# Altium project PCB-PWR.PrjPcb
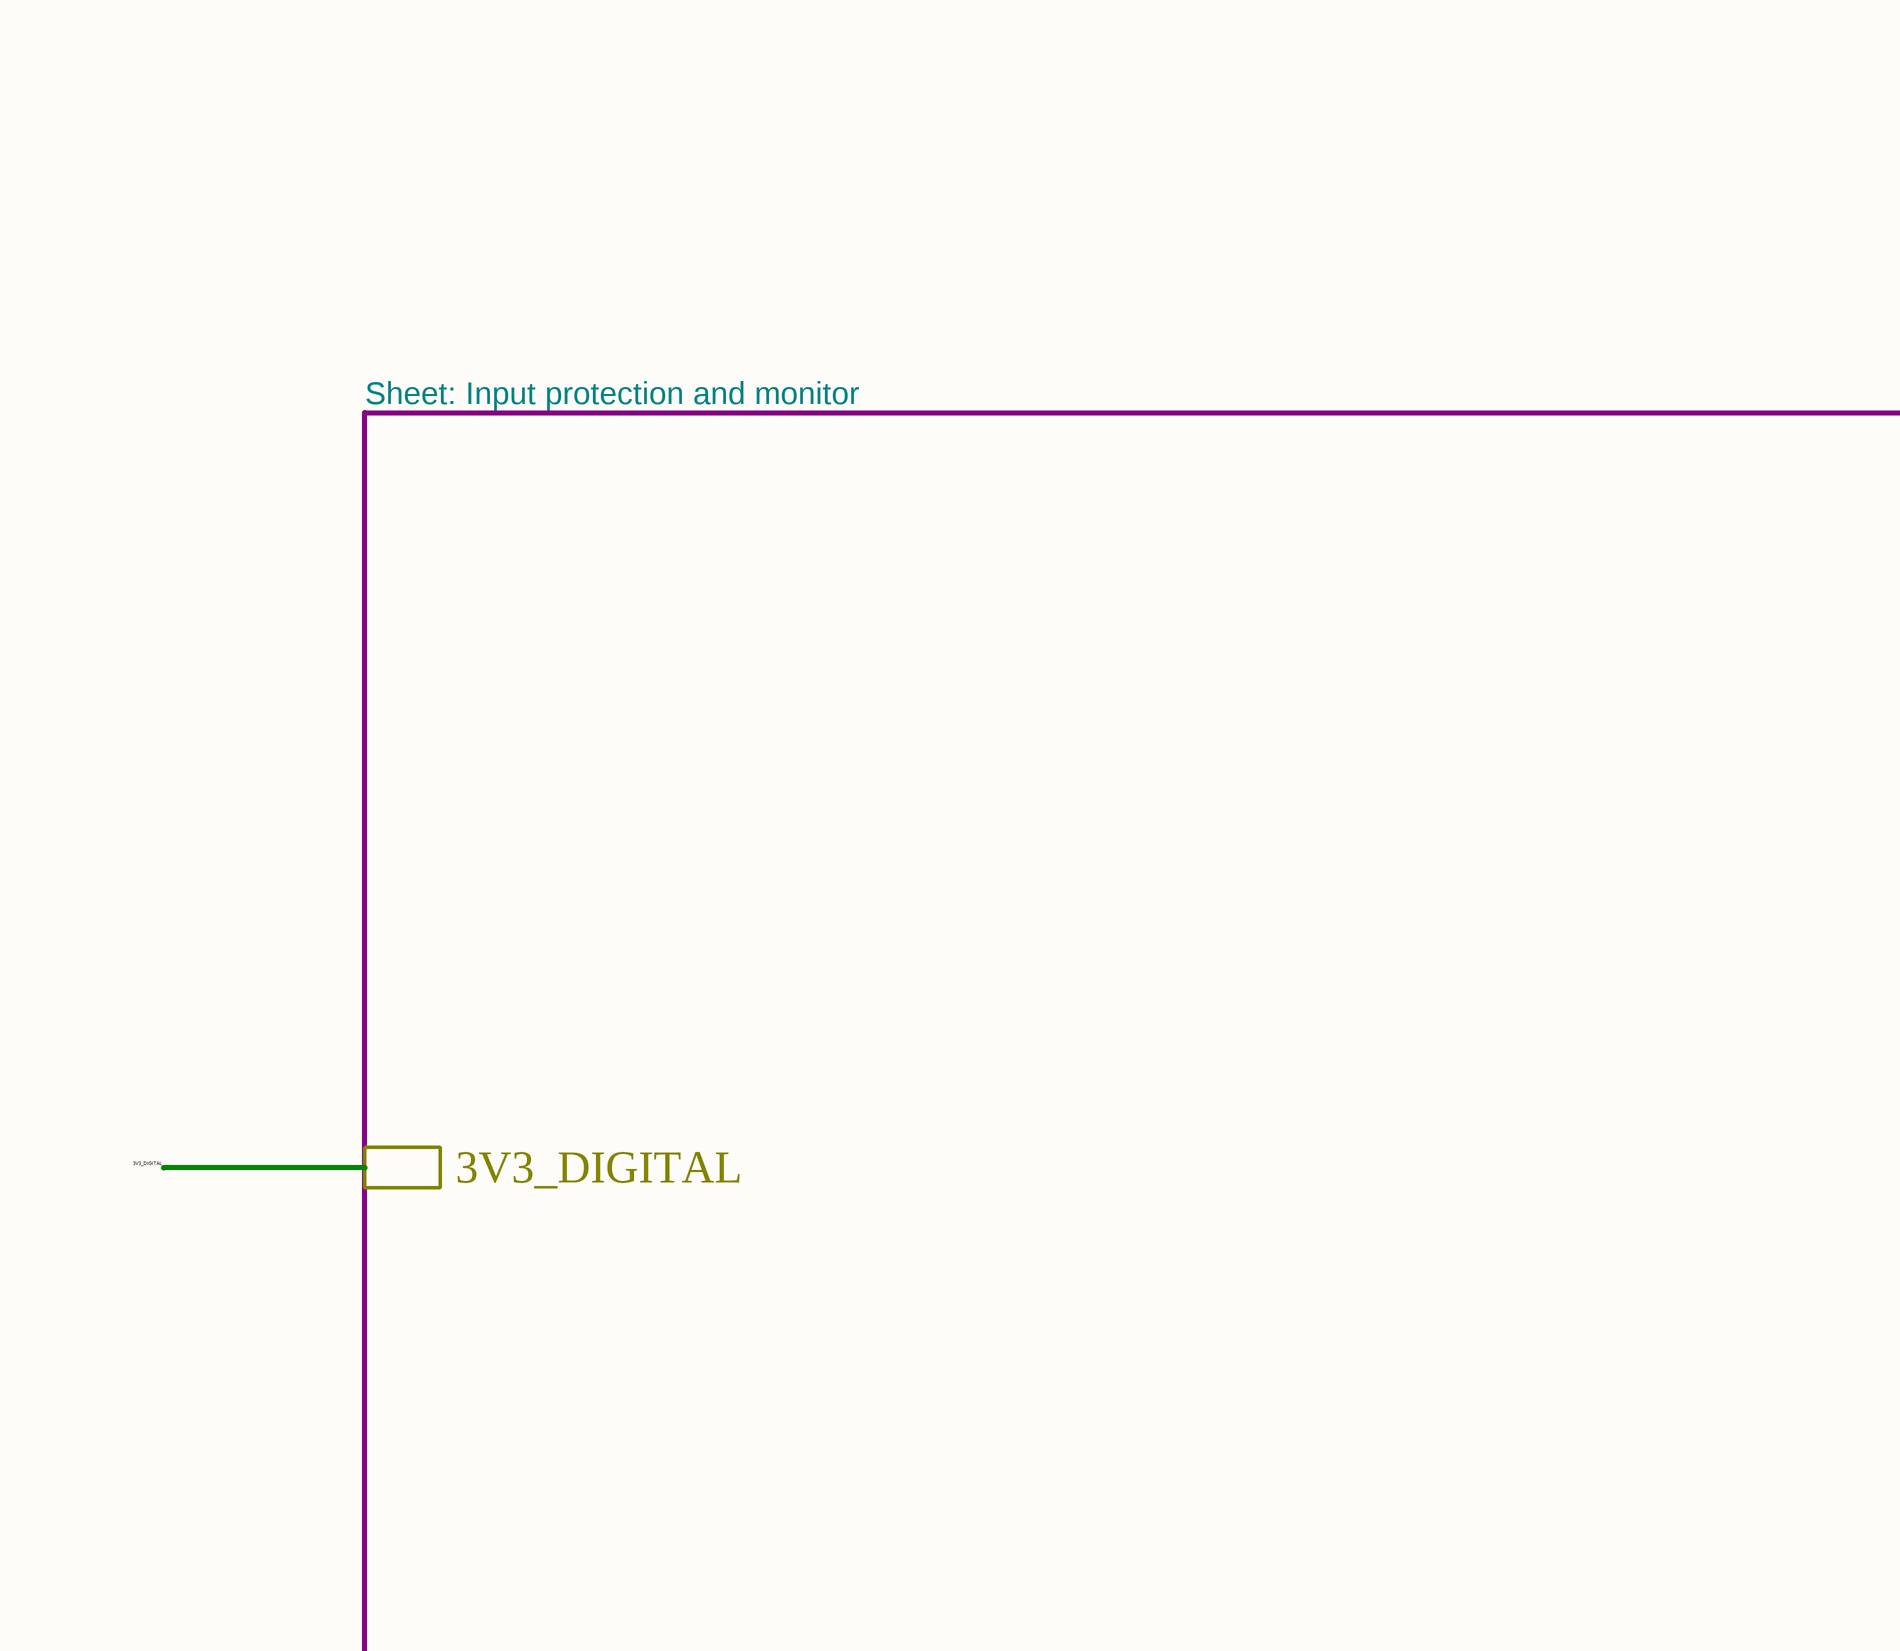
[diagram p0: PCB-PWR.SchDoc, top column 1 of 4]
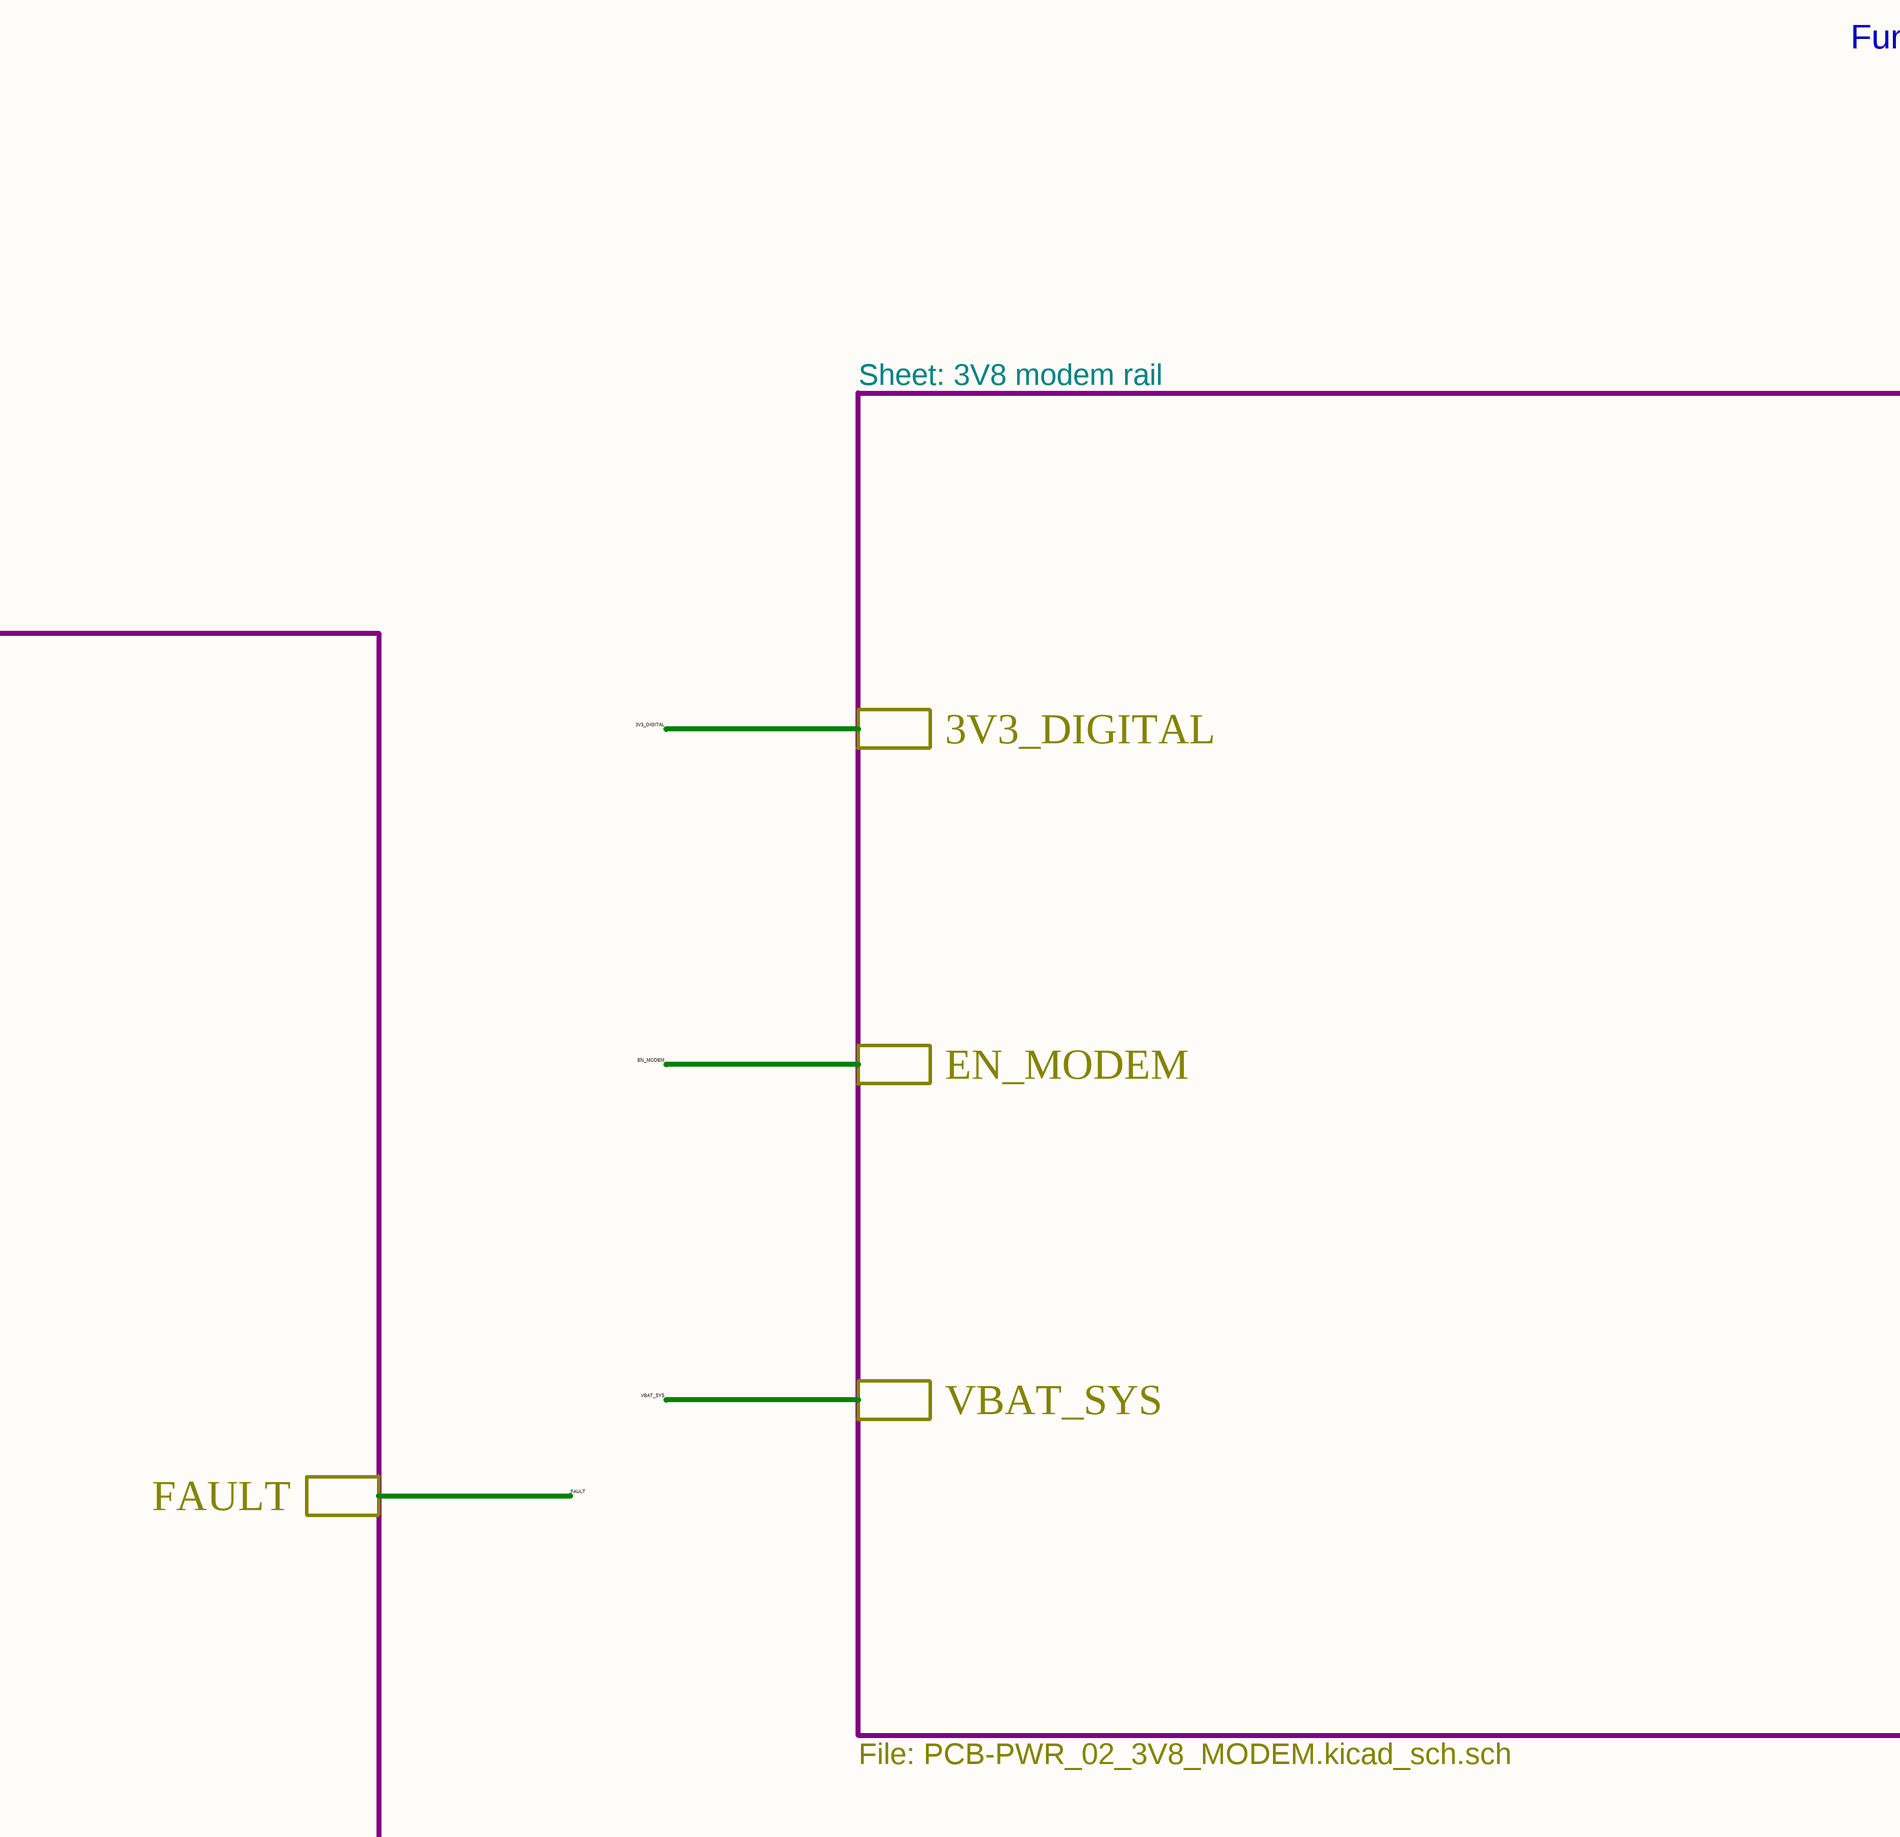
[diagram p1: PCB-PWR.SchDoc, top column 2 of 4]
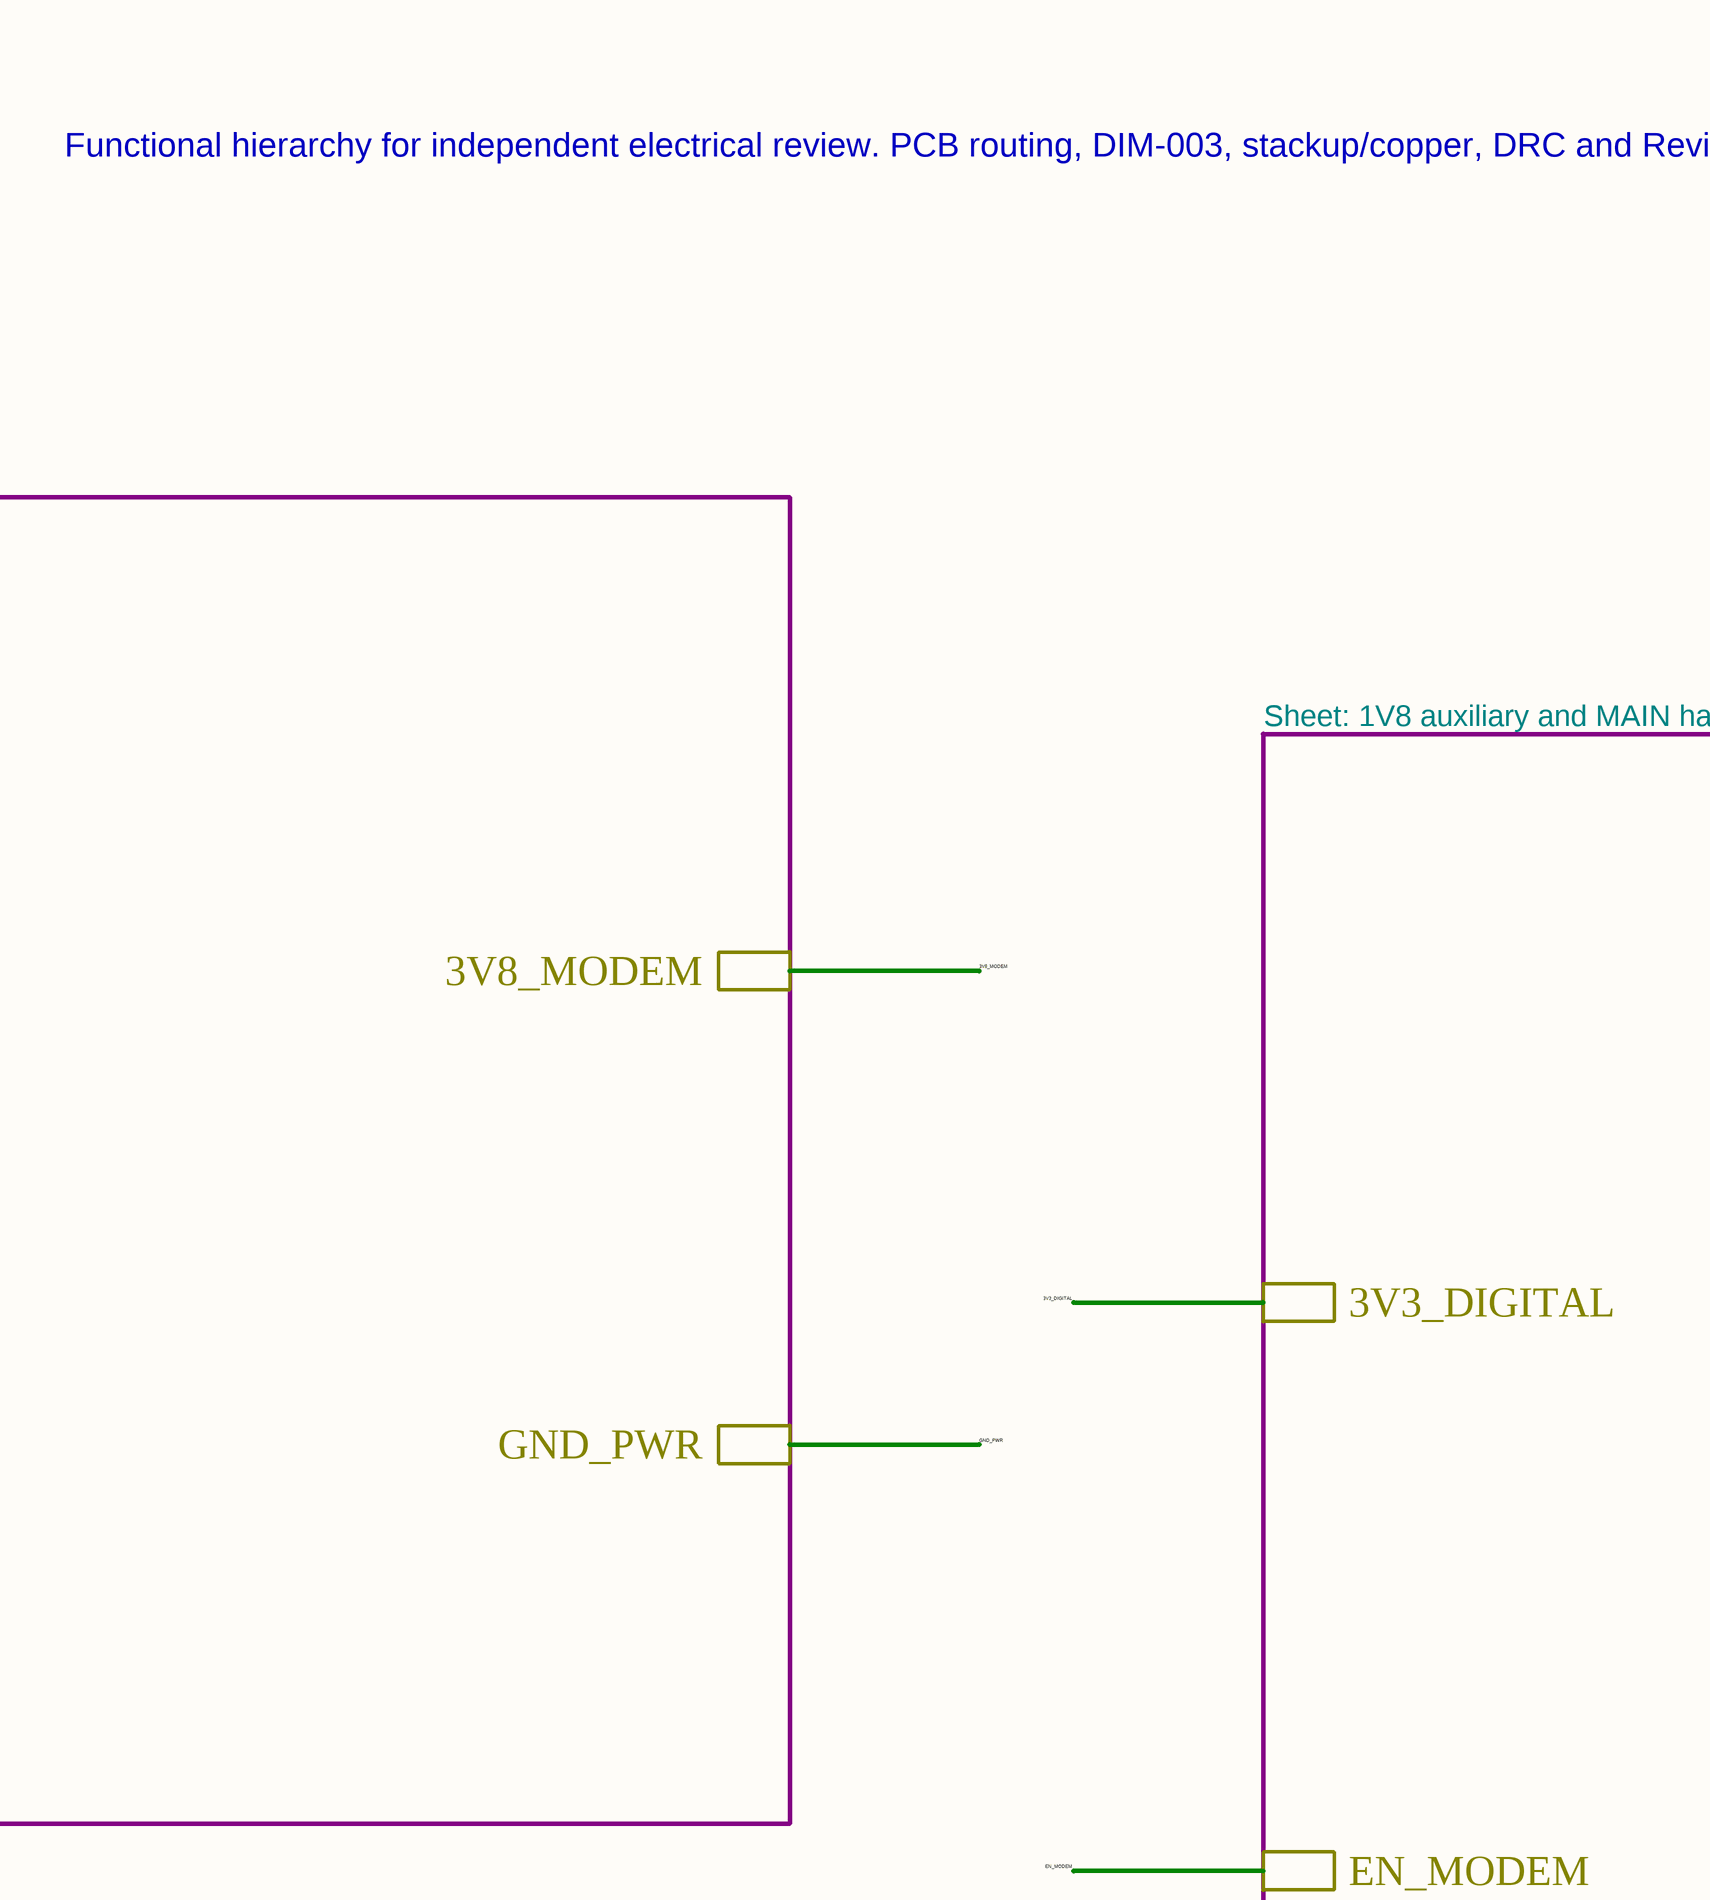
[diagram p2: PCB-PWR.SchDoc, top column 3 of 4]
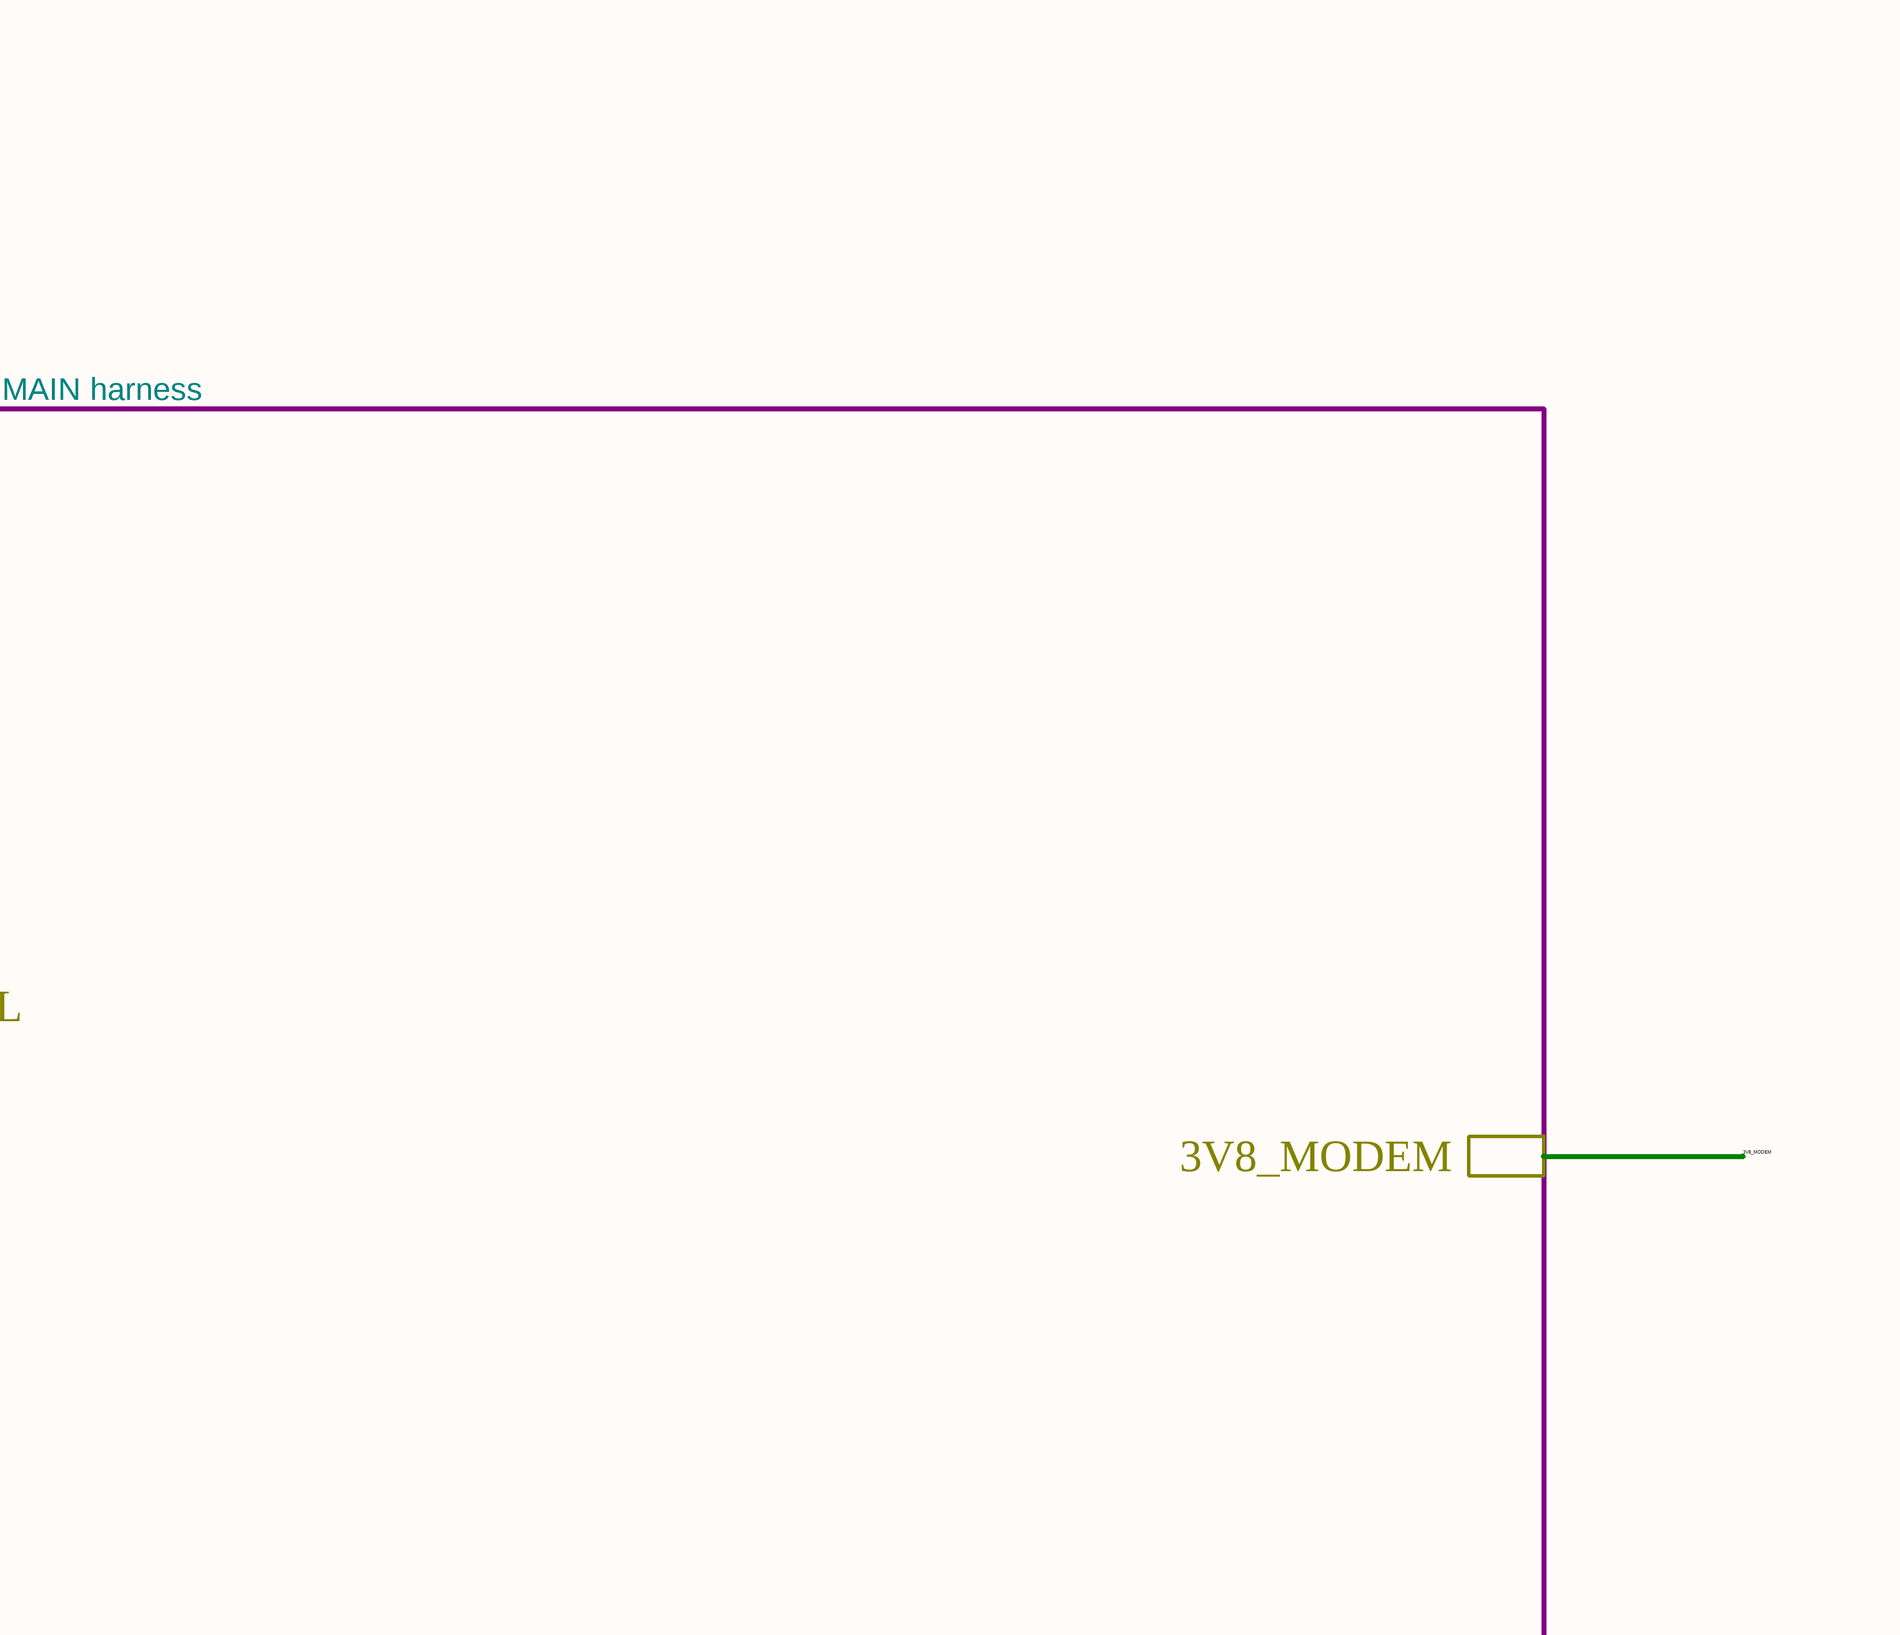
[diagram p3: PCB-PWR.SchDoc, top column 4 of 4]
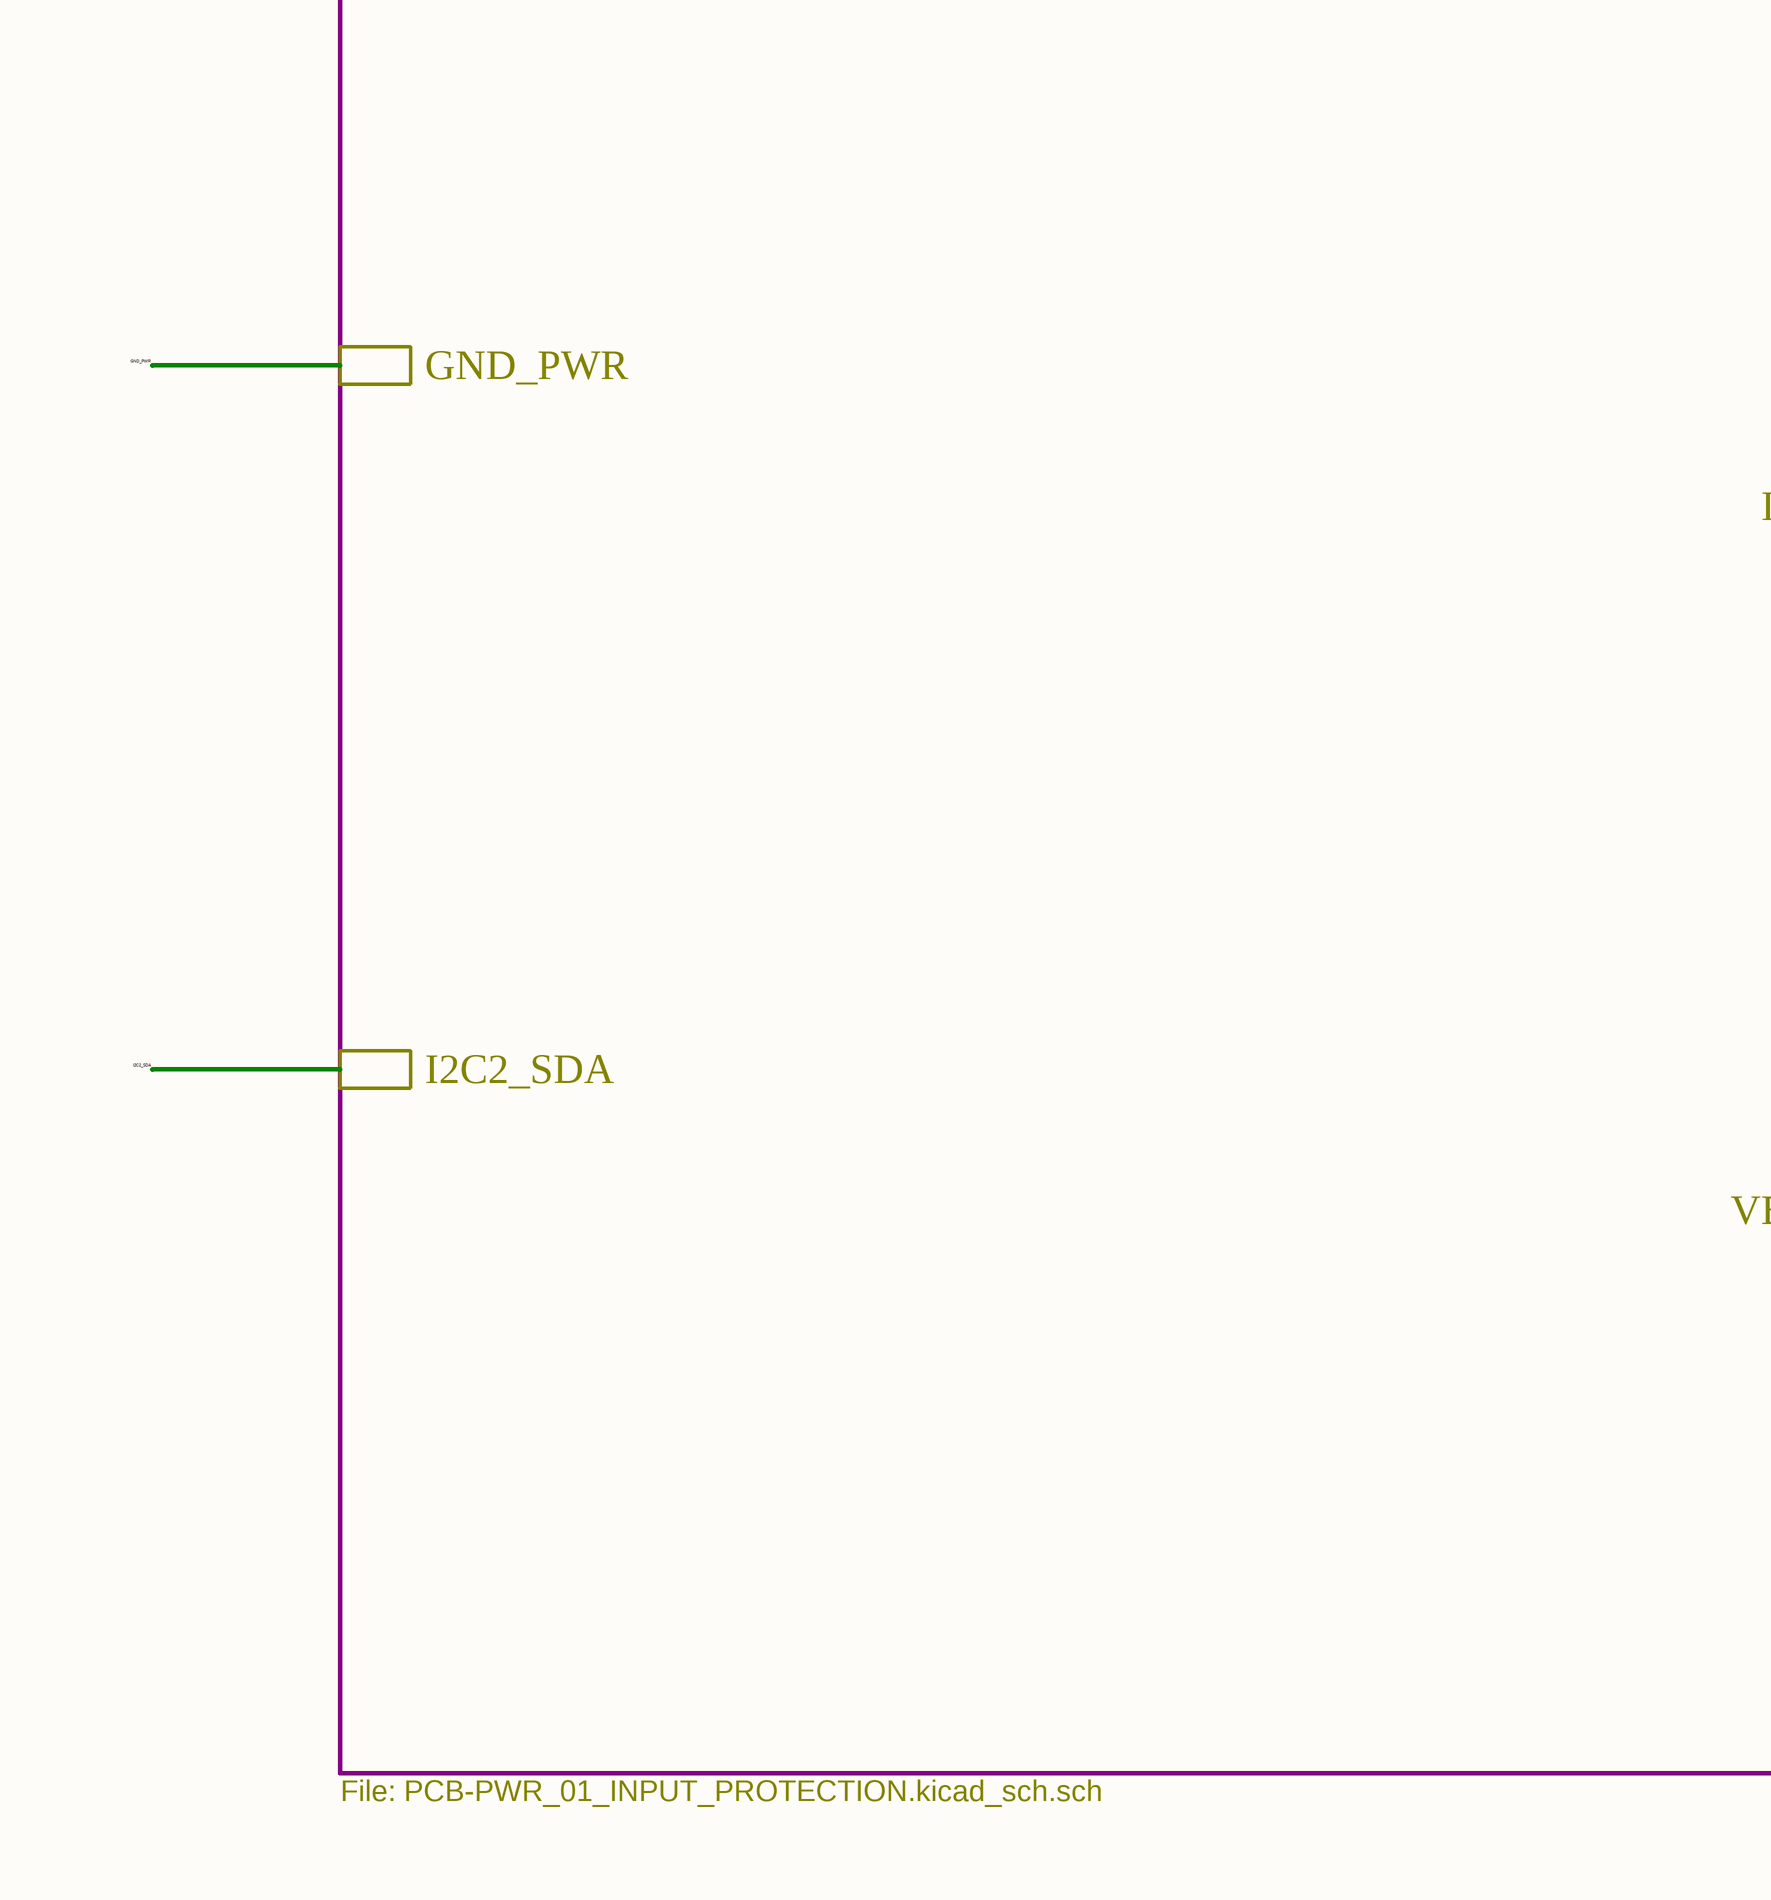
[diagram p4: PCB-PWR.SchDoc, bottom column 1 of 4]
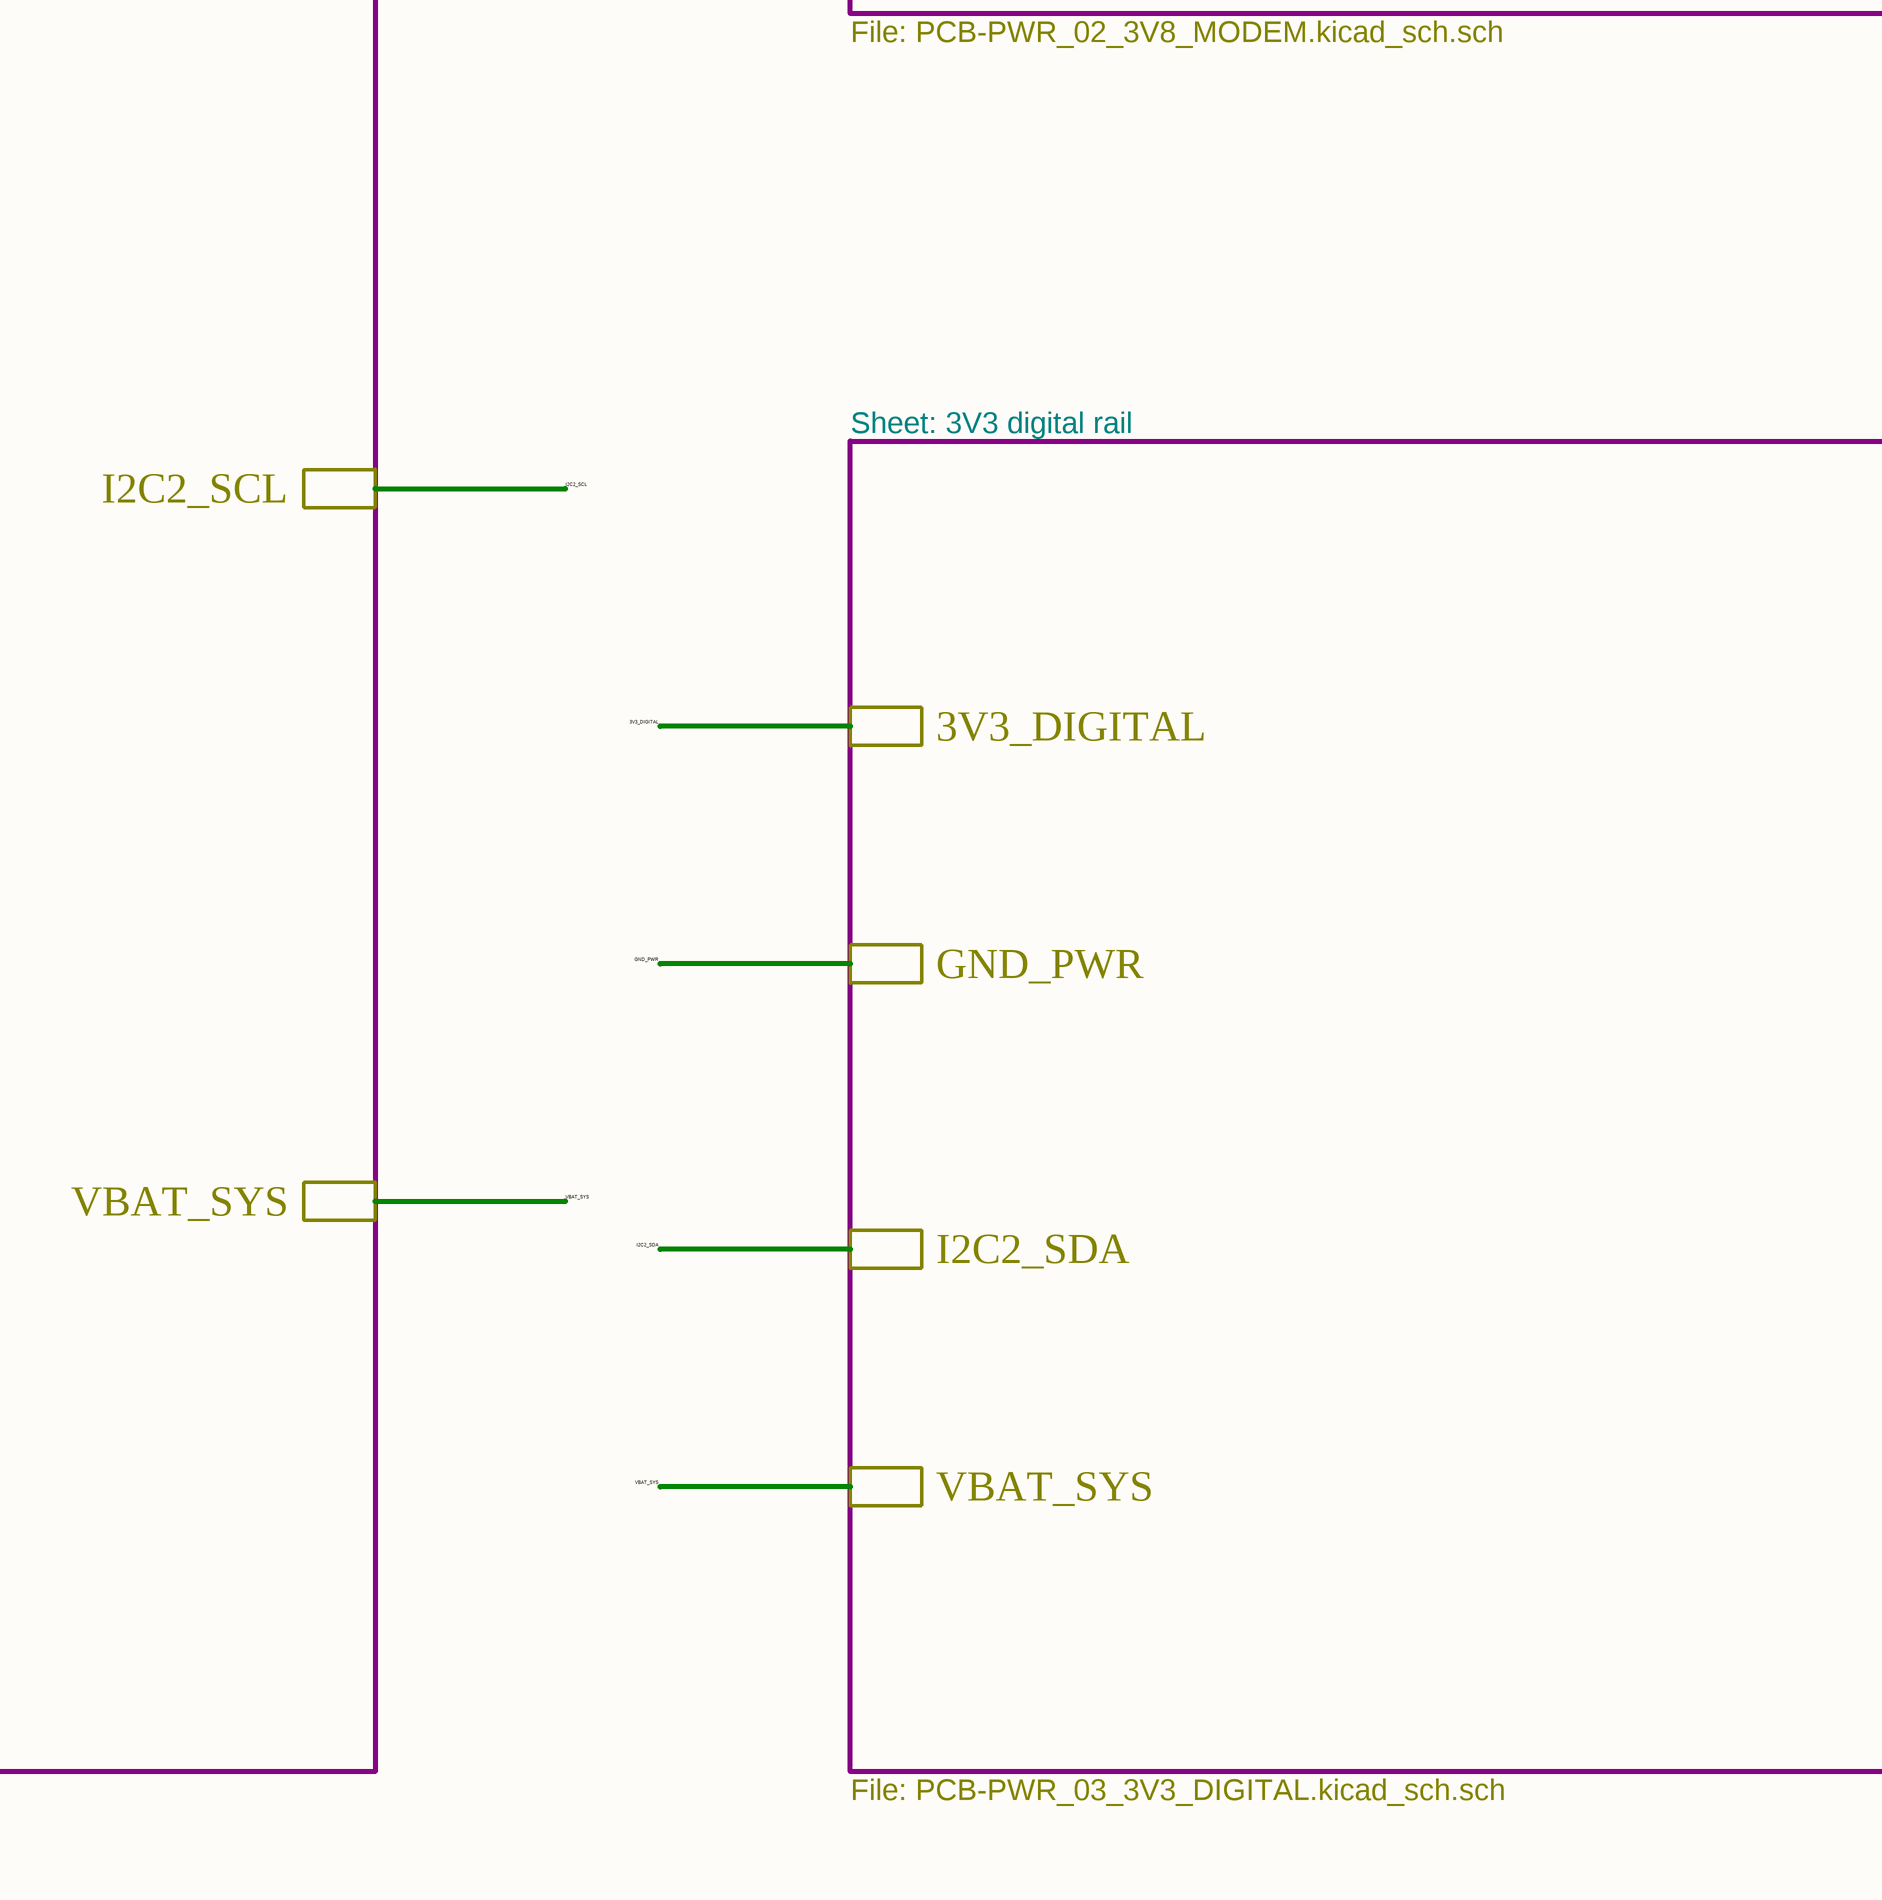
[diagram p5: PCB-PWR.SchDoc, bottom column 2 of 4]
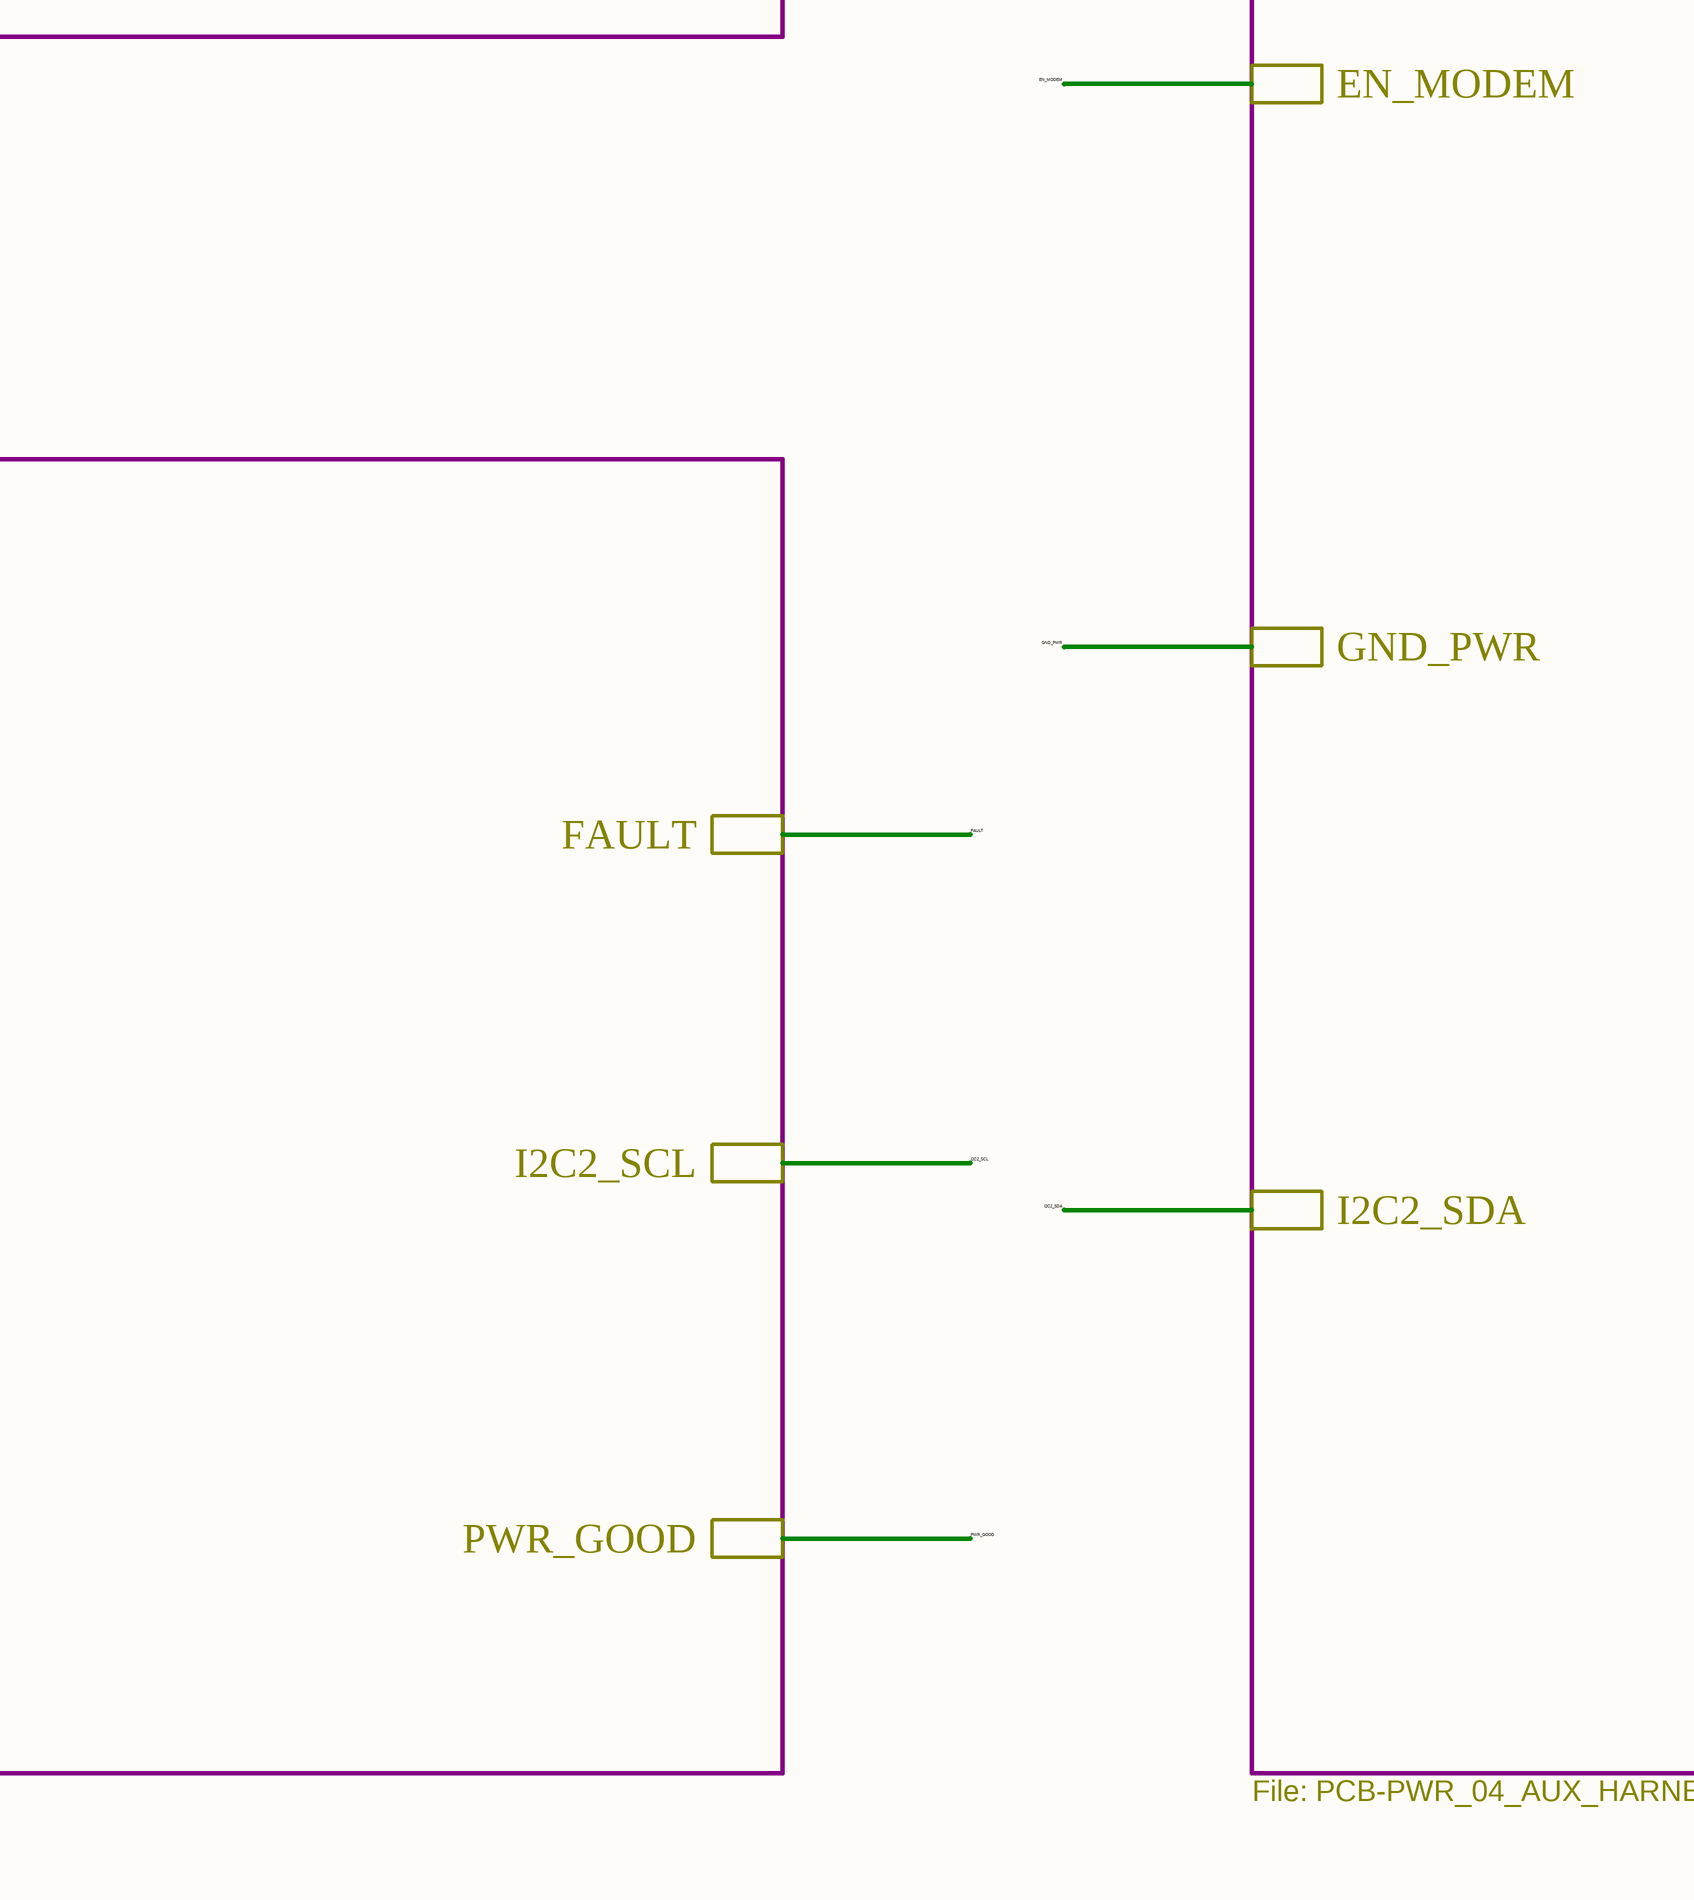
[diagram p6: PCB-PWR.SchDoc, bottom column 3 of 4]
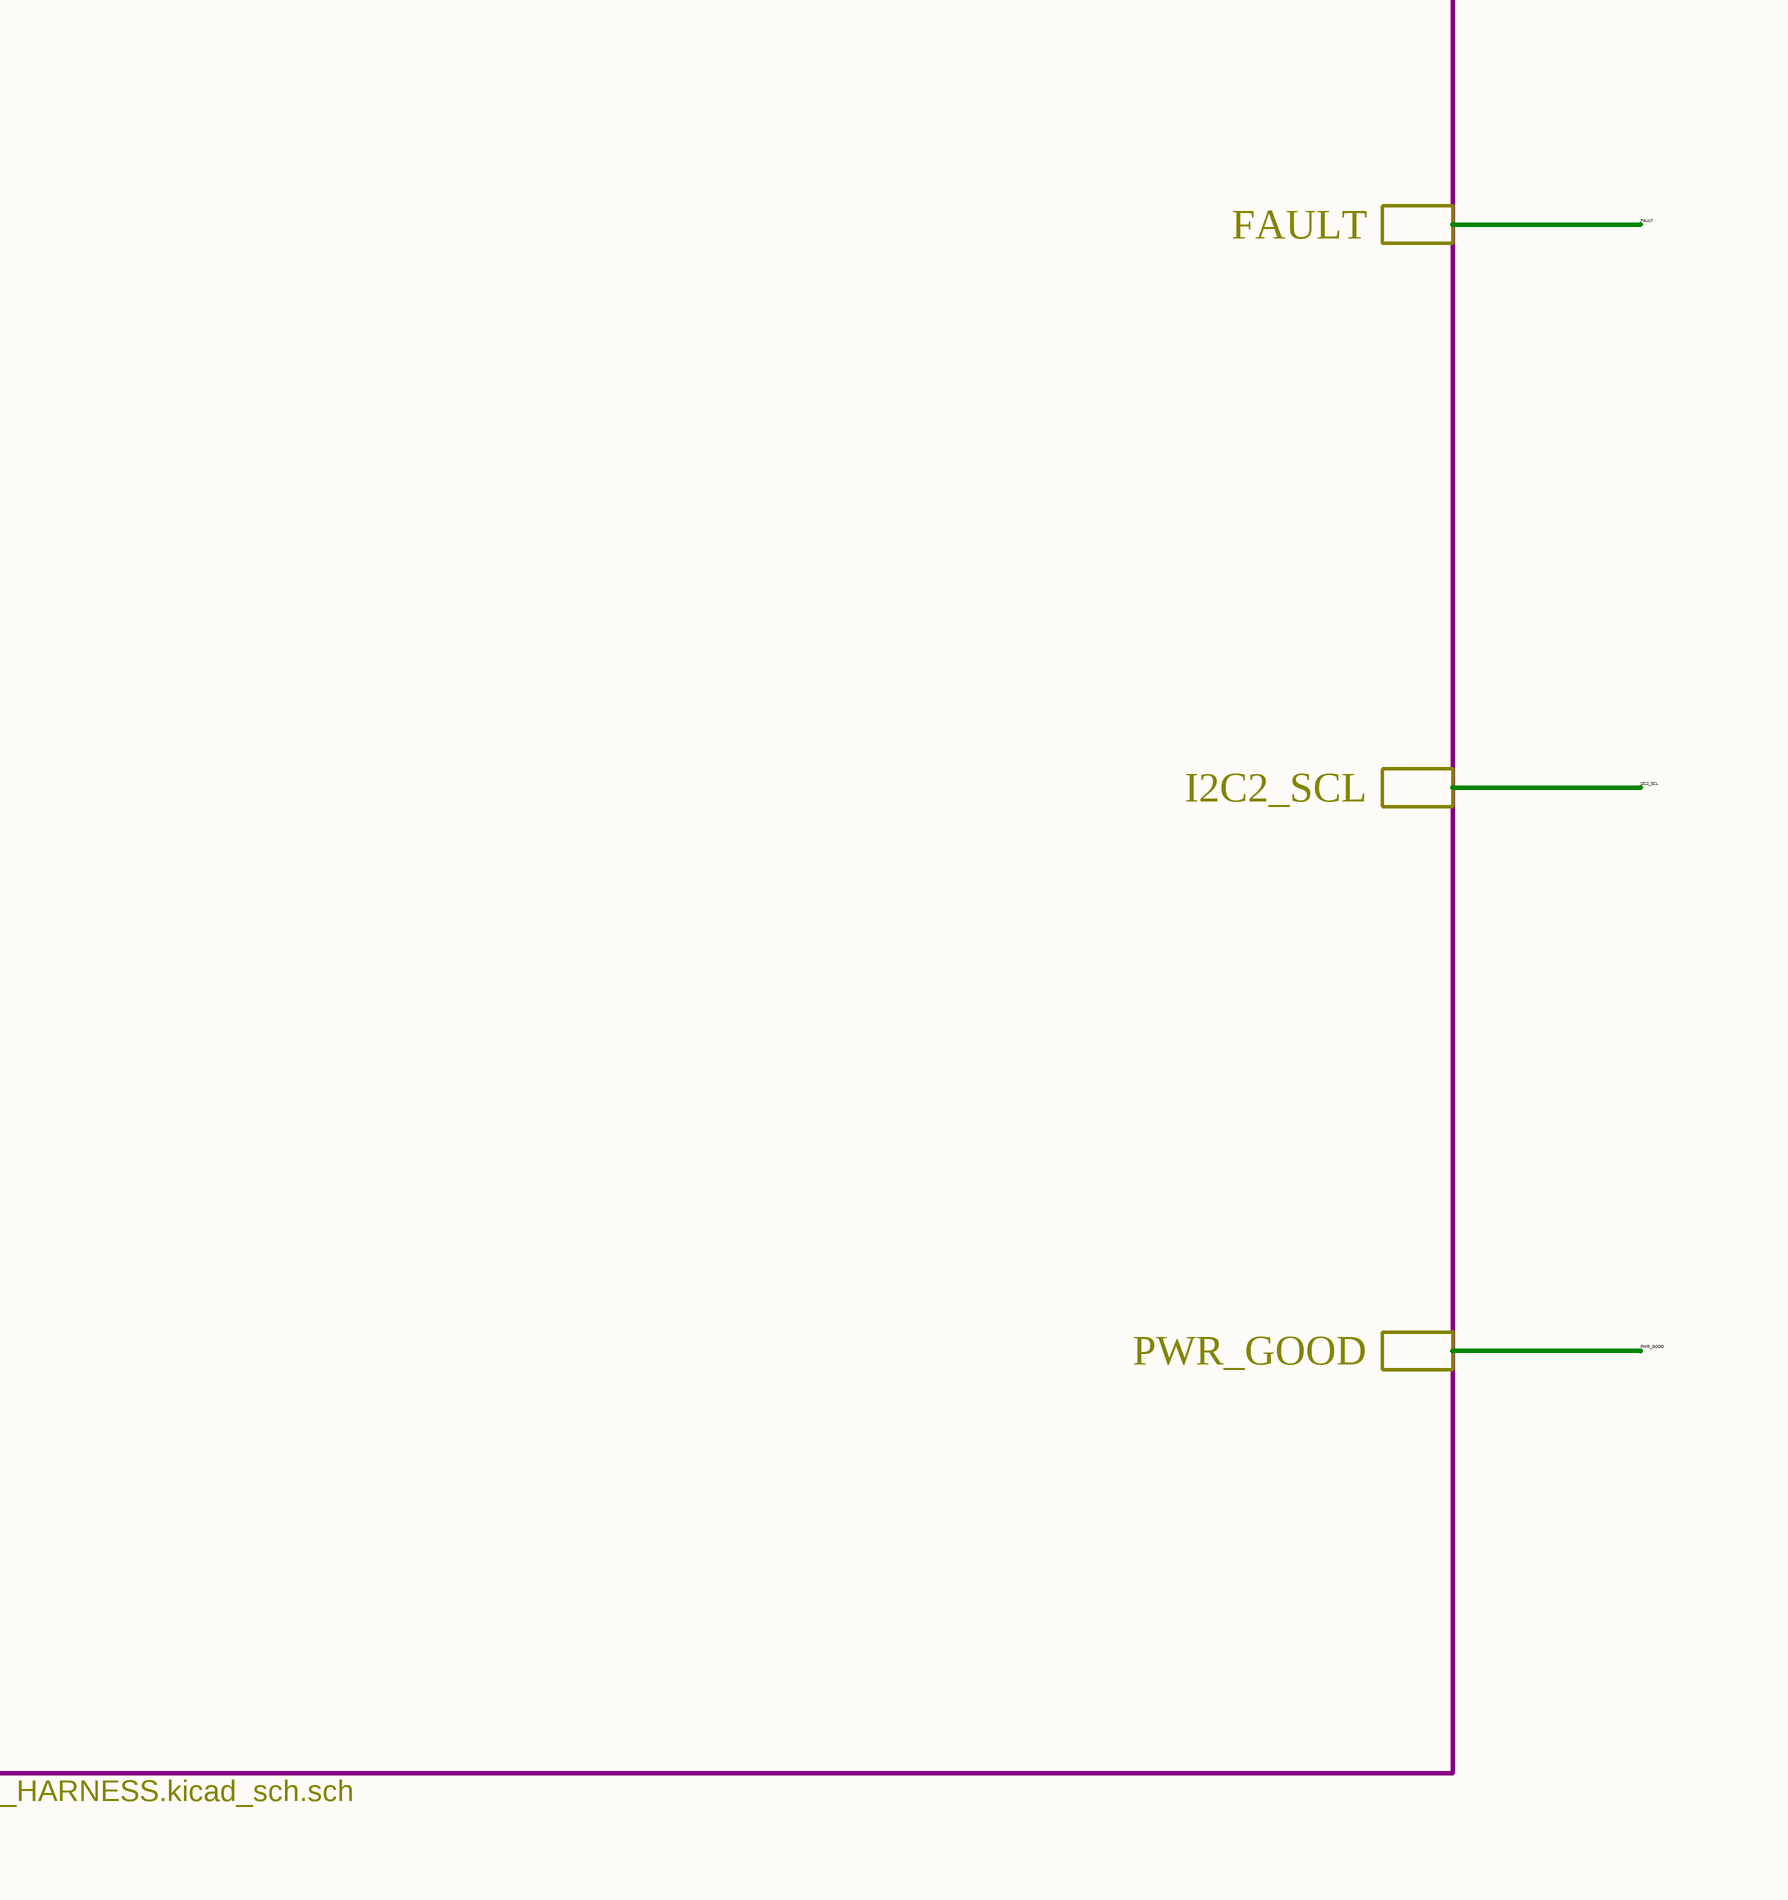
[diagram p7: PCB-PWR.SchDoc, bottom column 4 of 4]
5 sheets, 65 parts. Net scope: hierarchical (ports join the sheet entries above them; power ports are global).
Board file: PCB-PWR.PcbDoc
Sheets:
  PCB-PWR.SchDoc
    Input protection and monitor = PCB-PWR_01_INPUT_PROTECTION.SchDoc
    3V8 modem rail = PCB-PWR_02_3V8_MODEM.SchDoc
    3V3 digital rail = PCB-PWR_03_3V3_DIGITAL.SchDoc
    1V8 auxiliary and MAIN harness = PCB-PWR_04_AUX_HARNESS.SchDoc

## Sheet PCB-PWR.SchDoc
size 420 x 297 mm

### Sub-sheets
1V8 auxiliary and MAIN harness = PCB-PWR_04_AUX_HARNESS.SchDoc: 3V3_DIGITAL, EN_MODEM, GND_PWR, I2C2_SDA, 3V8_MODEM, FAULT, I2C2_SCL, PWR_GOOD
3V3 digital rail = PCB-PWR_03_3V3_DIGITAL.SchDoc: 3V3_DIGITAL, GND_PWR, I2C2_SDA, VBAT_SYS, FAULT, I2C2_SCL, PWR_GOOD
3V8 modem rail = PCB-PWR_02_3V8_MODEM.SchDoc: 3V3_DIGITAL, EN_MODEM, VBAT_SYS, 3V8_MODEM, GND_PWR
Input protection and monitor = PCB-PWR_01_INPUT_PROTECTION.SchDoc: 3V3_DIGITAL, GND_PWR, I2C2_SDA, FAULT, I2C2_SCL, VBAT_SYS

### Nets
3V3_DIGITAL: sheet Input protection and monitor/3V3_DIGITAL, sheet 3V8 modem rail/3V3_DIGITAL, sheet 3V3 digital rail/3V3_DIGITAL, sheet 1V8 auxiliary and MAIN harness/3V3_DIGITAL
3V8_MODEM: sheet 3V8 modem rail/3V8_MODEM, sheet 1V8 auxiliary and MAIN harness/3V8_MODEM
EN_MODEM: sheet 3V8 modem rail/EN_MODEM, sheet 1V8 auxiliary and MAIN harness/EN_MODEM
FAULT: sheet Input protection and monitor/FAULT, sheet 3V3 digital rail/FAULT, sheet 1V8 auxiliary and MAIN harness/FAULT
GND_PWR: sheet Input protection and monitor/GND_PWR, sheet 3V8 modem rail/GND_PWR, sheet 3V3 digital rail/GND_PWR, sheet 1V8 auxiliary and MAIN harness/GND_PWR
I2C2_SCL: sheet Input protection and monitor/I2C2_SCL, sheet 3V3 digital rail/I2C2_SCL, sheet 1V8 auxiliary and MAIN harness/I2C2_SCL
I2C2_SDA: sheet Input protection and monitor/I2C2_SDA, sheet 3V3 digital rail/I2C2_SDA, sheet 1V8 auxiliary and MAIN harness/I2C2_SDA
PWR_GOOD: sheet 3V3 digital rail/PWR_GOOD, sheet 1V8 auxiliary and MAIN harness/PWR_GOOD
VBAT_SYS: sheet Input protection and monitor/VBAT_SYS, sheet 3V8 modem rail/VBAT_SYS, sheet 3V3 digital rail/VBAT_SYS

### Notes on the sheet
- Functional hierarchy for independent electrical review. PCB routing, DIM-003, stackup/copper, DRC and Review B remain open.
- Sheet: 3V8 modem rail
- Sheet: Input protection and monitor
- Sheet: 1V8 auxiliary and MAIN harness
- File: PCB-PWR_02_3V8_MODEM.kicad_sch.sch
- Sheet: 3V3 digital rail
- File: PCB-PWR_01_INPUT_PROTECTION.kicad_sch.sch
- File: PCB-PWR_03_3V3_DIGITAL.kicad_sch.sch
- File: PCB-PWR_04_AUX_HARNESS.kicad_sch.sch

## Sheet PCB-PWR_01_INPUT_PROTECTION.SchDoc
size 420 x 297 mm
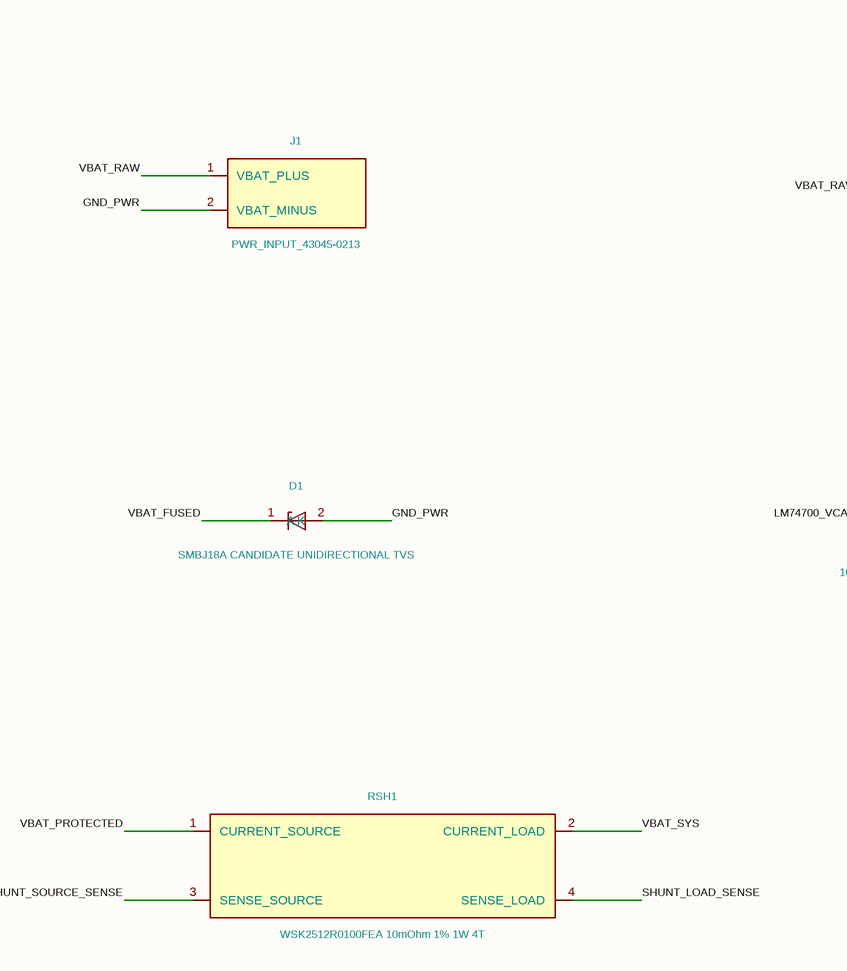
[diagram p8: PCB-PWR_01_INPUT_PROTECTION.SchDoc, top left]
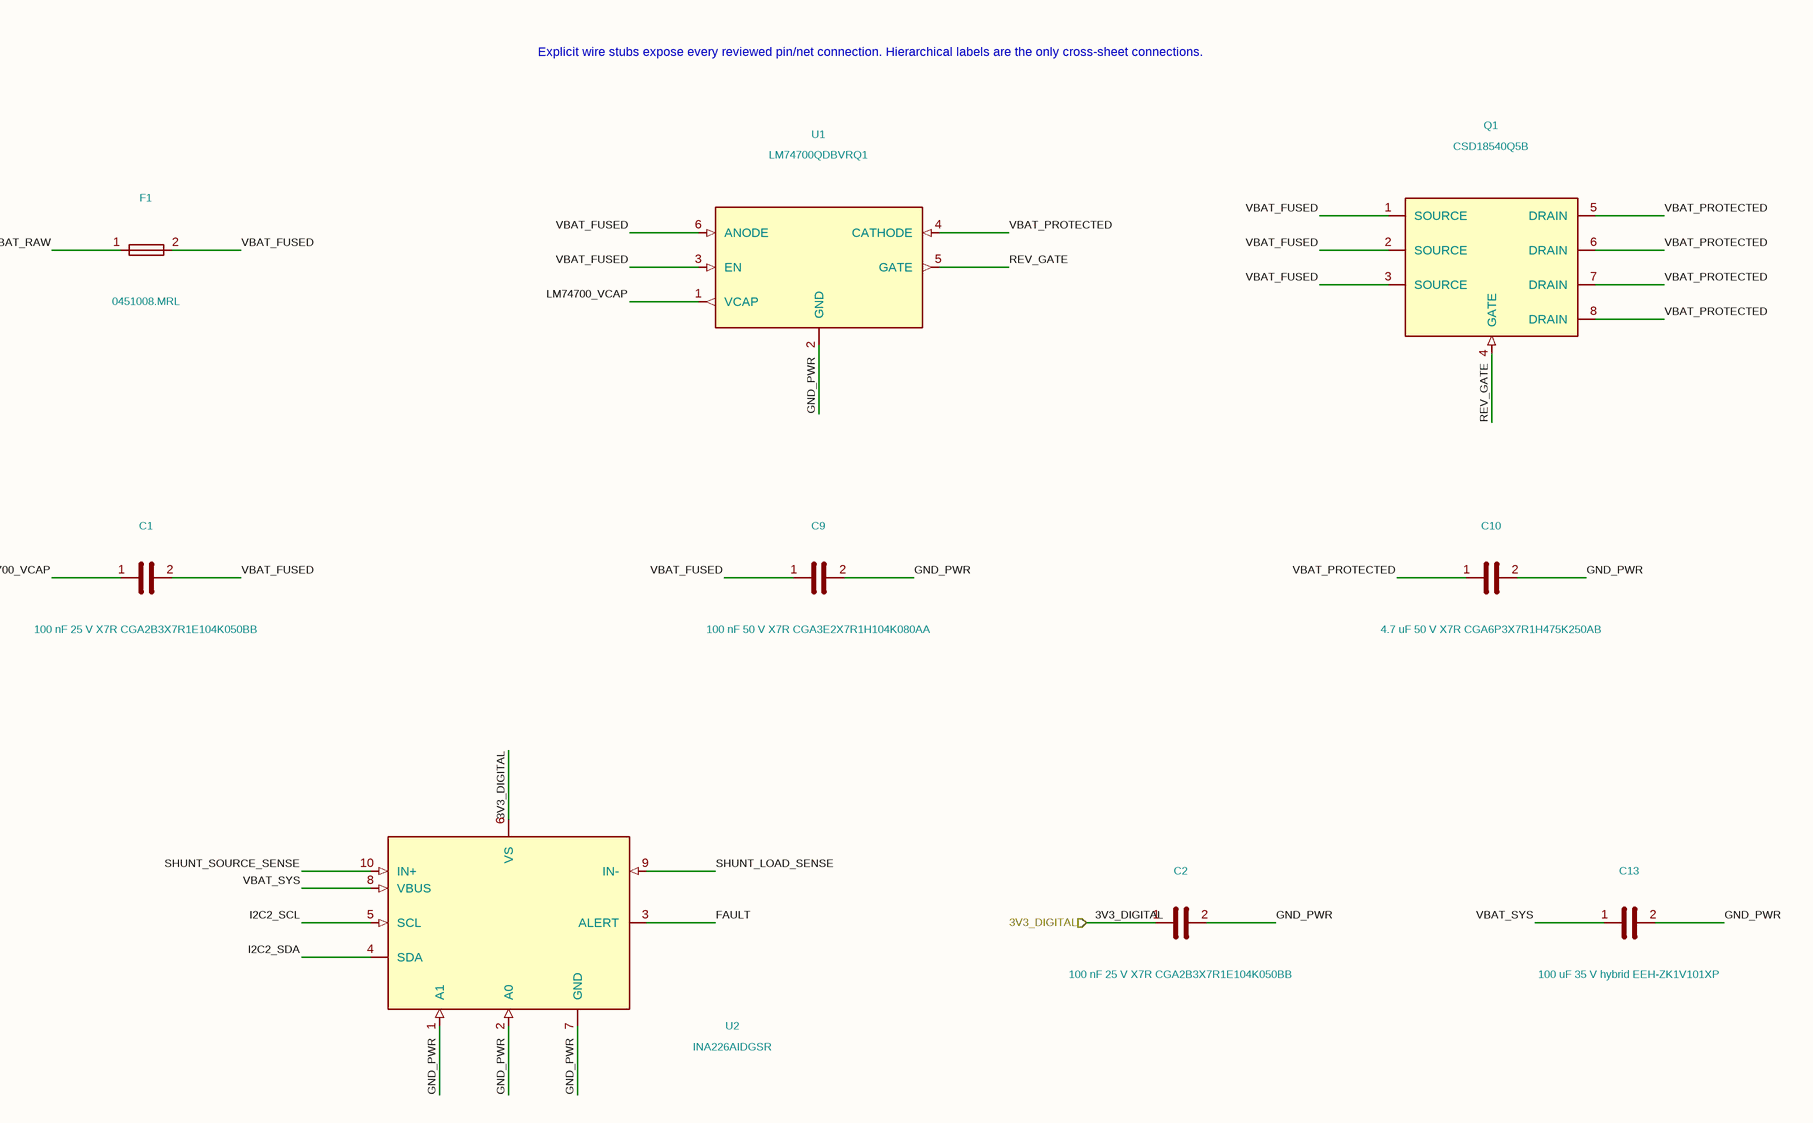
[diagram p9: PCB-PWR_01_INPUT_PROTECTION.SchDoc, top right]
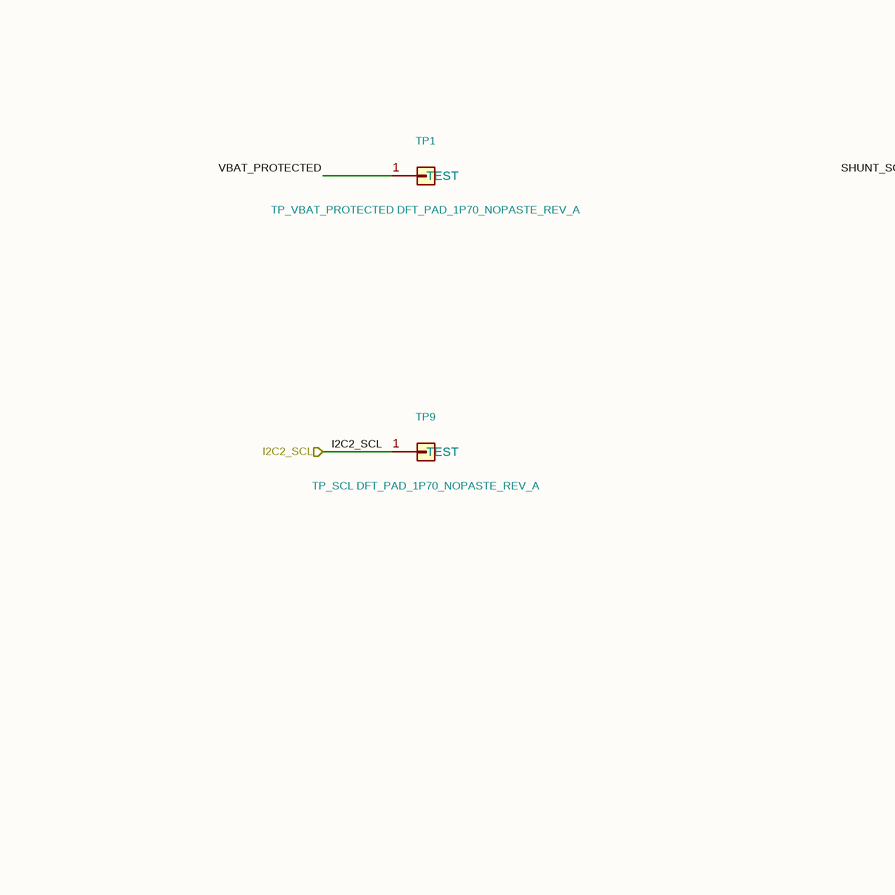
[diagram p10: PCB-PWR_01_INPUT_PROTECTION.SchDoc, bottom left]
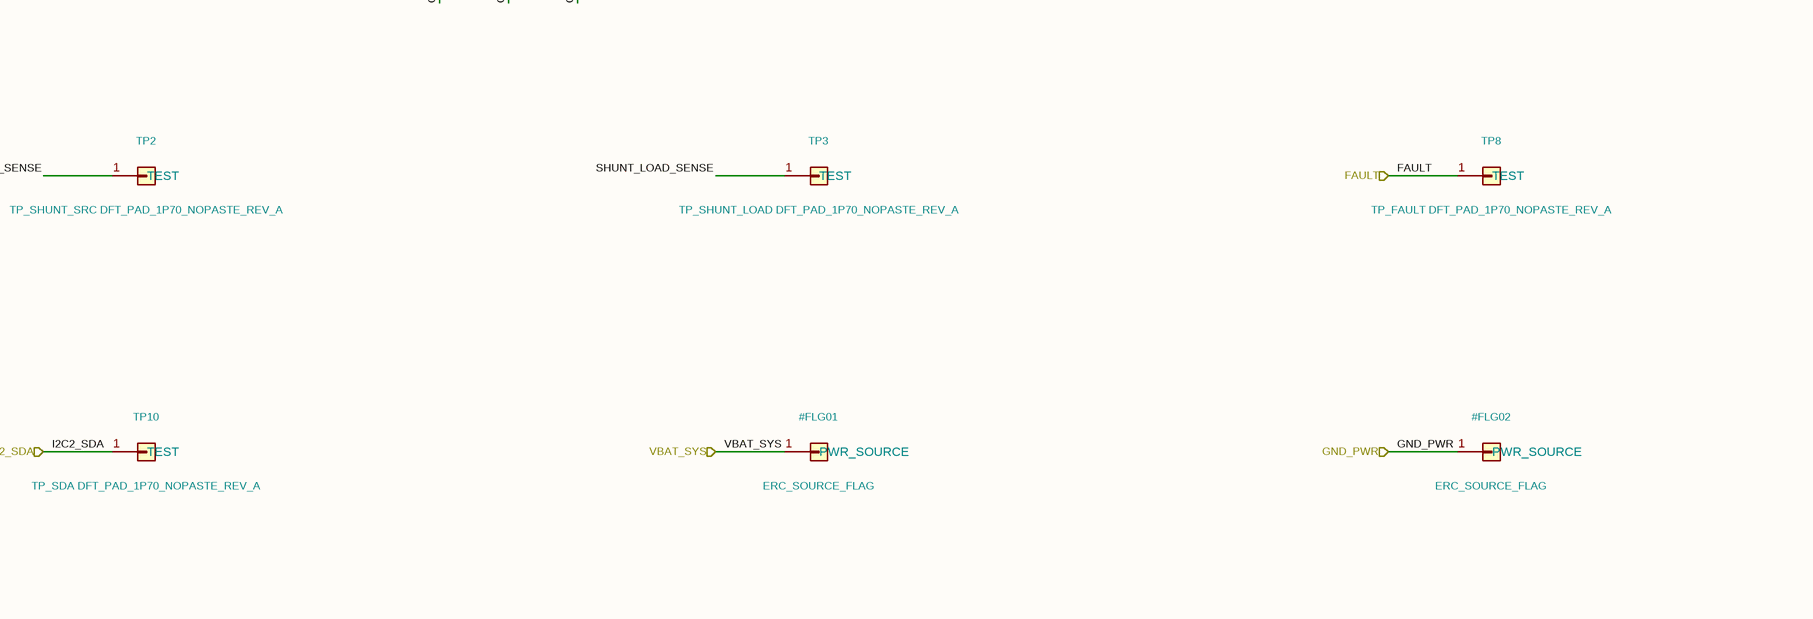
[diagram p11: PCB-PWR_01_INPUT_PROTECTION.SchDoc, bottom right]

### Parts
#FLG01  ERC_SOURCE_FLAG
#FLG02  ERC_SOURCE_FLAG
C1  100 nF 25 V X7R CGA2B3X7R1E104K050BB  [C_0402_1005Metric]
C2  100 nF 25 V X7R CGA2B3X7R1E104K050BB  [C_0402_1005Metric]
C9  100 nF 50 V X7R CGA3E2X7R1H104K080AA  [C_0603_1608Metric]
C10  4.7 uF 50 V X7R CGA6P3X7R1H475K250AB  [C_1210_3225Metric]
C13  100 uF 35 V hybrid EEH-ZK1V101XP  [CP_Elec_6.3x7.7]
D1  SMBJ18A CANDIDATE UNIDIRECTIONAL TVS  [D_SMB]
F1  0451008.MRL  [Fuse_1206_3216Metric]
J1  PWR_INPUT_43045-0213  [Molex_43045-0213_MicroFit-2_Vertical]
Q1  CSD18540Q5B  [CSD18540Q5B_DNK]
RSH1  WSK2512R0100FEA 10mOhm 1% 1W 4T  [Vishay_WSK2512_4T_T1.19mm]
TP1  TP_VBAT_PROTECTED DFT_PAD_1P70_NOPASTE_REV_A  [TestPoint_DFT_1.7mm_NoPaste]
TP2  TP_SHUNT_SRC DFT_PAD_1P70_NOPASTE_REV_A  [TestPoint_DFT_1.7mm_NoPaste]
TP3  TP_SHUNT_LOAD DFT_PAD_1P70_NOPASTE_REV_A  [TestPoint_DFT_1.7mm_NoPaste]
TP8  TP_FAULT DFT_PAD_1P70_NOPASTE_REV_A  [TestPoint_DFT_1.7mm_NoPaste]
TP9  TP_SCL DFT_PAD_1P70_NOPASTE_REV_A  [TestPoint_DFT_1.7mm_NoPaste]
TP10  TP_SDA DFT_PAD_1P70_NOPASTE_REV_A  [TestPoint_DFT_1.7mm_NoPaste]
U1  LM74700QDBVRQ1  [TI_DBV0006A_SOT23-6]
U2  INA226AIDGSR  [TI_DGS0010A_VSSOP10]

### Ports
3V3_DIGITAL, FAULT, GND_PWR, I2C2_SCL, I2C2_SDA, VBAT_SYS

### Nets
3V3_DIGITAL: C2.1 U2.6(VS) ; port 3V3_DIGITAL
FAULT: TP8.1(TEST) U2.3(ALERT) ; port FAULT
GND_PWR: #FLG02.1(PWR_SOURCE) C2.2 C9.2 C10.2 C13.2 D1.2(A) J1.2(VBAT_MINUS) U1.2(GND) U2.1(A1) U2.2(A0) U2.7(GND) ; port GND_PWR
I2C2_SCL: TP9.1(TEST) U2.5(SCL) ; port I2C2_SCL
I2C2_SDA: TP10.1(TEST) U2.4(SDA) ; port I2C2_SDA
LM74700_VCAP: C1.1 U1.1(VCAP)
REV_GATE: Q1.4(GATE) U1.5(GATE)
SHUNT_LOAD_SENSE: RSH1.4(SENSE_LOAD) TP3.1(TEST) U2.9(IN-)
SHUNT_SOURCE_SENSE: RSH1.3(SENSE_SOURCE) TP2.1(TEST) U2.10(IN+)
VBAT_FUSED: C1.2 C9.1 D1.1(K) F1.2 Q1.1(SOURCE) Q1.2(SOURCE) Q1.3(SOURCE) U1.3(EN) U1.6(ANODE)
VBAT_PROTECTED: C10.1 Q1.5(DRAIN) Q1.6(DRAIN) Q1.7(DRAIN) Q1.8(DRAIN) RSH1.1(CURRENT_SOURCE) TP1.1(TEST) U1.4(CATHODE)
VBAT_RAW: F1.1 J1.1(VBAT_PLUS)
VBAT_SYS: #FLG01.1(PWR_SOURCE) C13.1 RSH1.2(CURRENT_LOAD) U2.8(VBUS) ; port VBAT_SYS

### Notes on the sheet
- Explicit wire stubs expose every reviewed pin/net connection. Hierarchical labels are the only cross-sheet connections.

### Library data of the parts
C1 C2 C9 C10 C13 = C
D1 = D_Zener
F1 = Fuse
J1 = Conn_01x02
Q1 = Conn_01x08
RSH1 = Conn_01x04
TP1-TP3 TP8-TP10 = TESTPOINT
U1 = Conn_01x06
U2 = Conn_01x10

## Sheet PCB-PWR_02_3V8_MODEM.SchDoc
size 420 x 297 mm
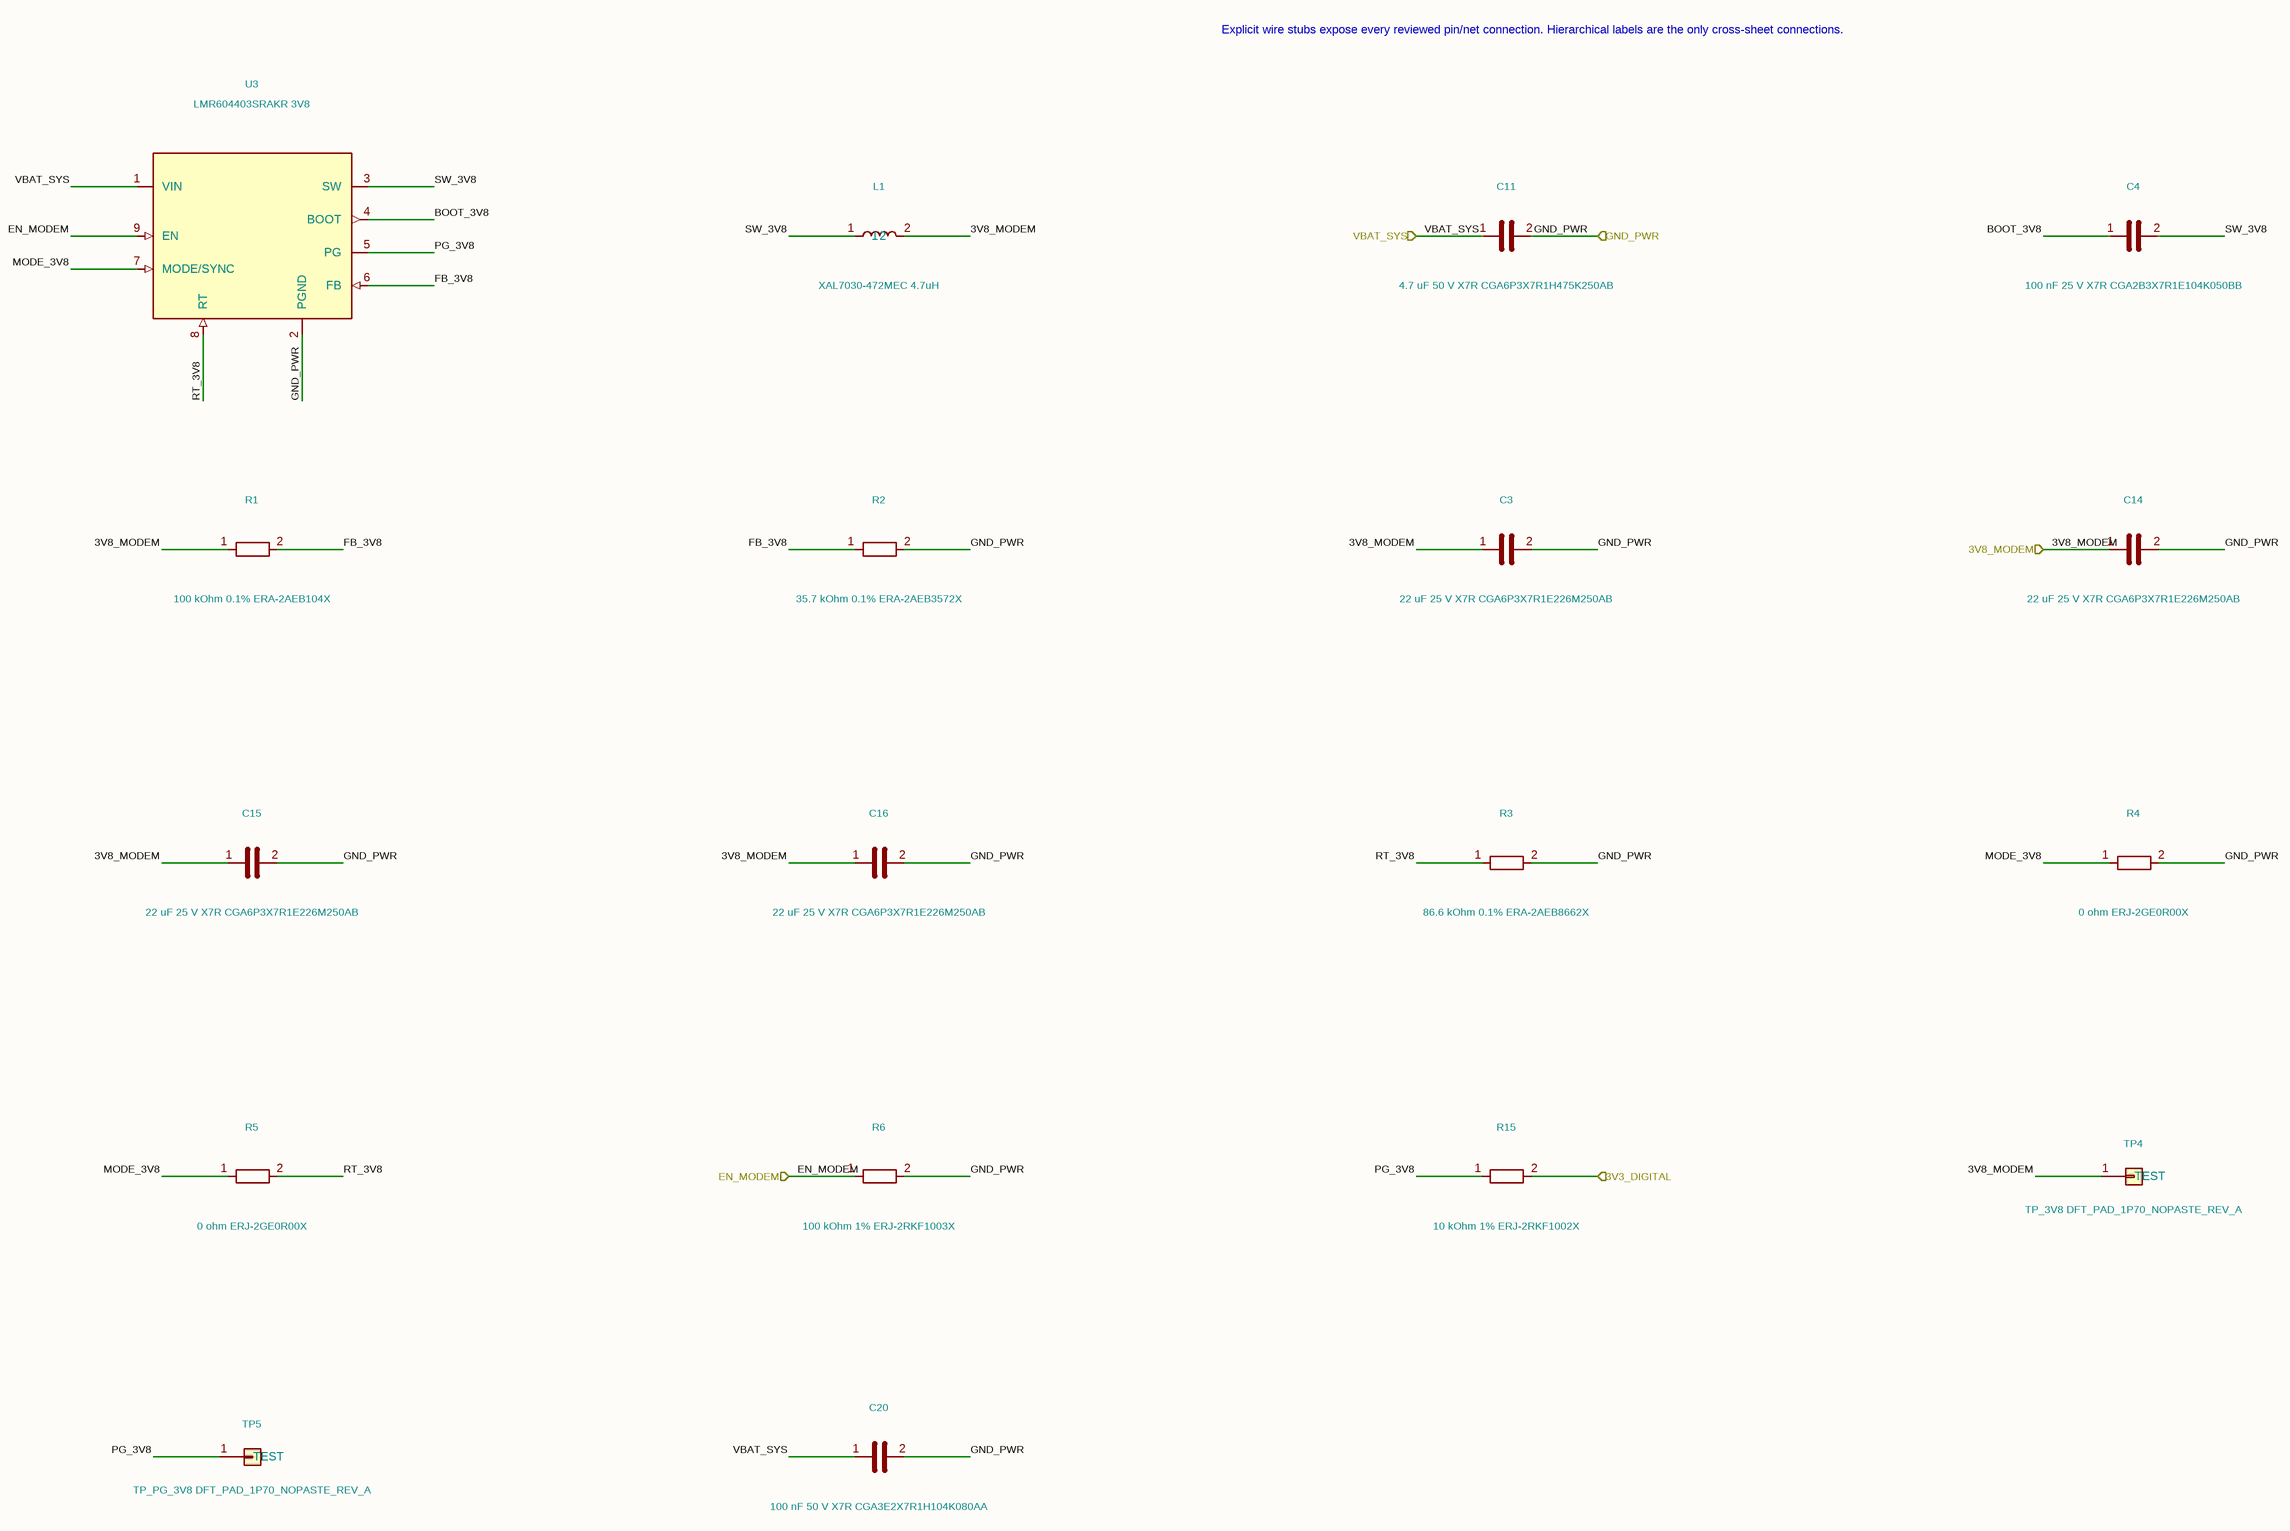
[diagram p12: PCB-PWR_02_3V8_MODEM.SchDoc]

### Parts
C3  22 uF 25 V X7R CGA6P3X7R1E226M250AB  [C_1210_3225Metric]
C4  100 nF 25 V X7R CGA2B3X7R1E104K050BB  [C_0402_1005Metric]
C11  4.7 uF 50 V X7R CGA6P3X7R1H475K250AB  [C_1210_3225Metric]
C14  22 uF 25 V X7R CGA6P3X7R1E226M250AB  [C_1210_3225Metric]
C15  22 uF 25 V X7R CGA6P3X7R1E226M250AB  [C_1210_3225Metric]
C16  22 uF 25 V X7R CGA6P3X7R1E226M250AB  [C_1210_3225Metric]
C20  100 nF 50 V X7R CGA3E2X7R1H104K080AA  [C_0603_1608Metric]
L1  XAL7030-472MEC 4.7uH  [Coilcraft_XAL7030_472]
R1  100 kOhm 0.1% ERA-2AEB104X  [R_0402_1005Metric]
R2  35.7 kOhm 0.1% ERA-2AEB3572X  [R_0402_1005Metric]
R3  86.6 kOhm 0.1% ERA-2AEB8662X  [R_0402_1005Metric]
R4  0 ohm ERJ-2GE0R00X  [R_0402_1005Metric]
R5  0 ohm ERJ-2GE0R00X  [R_0402_1005Metric]
R6  100 kOhm 1% ERJ-2RKF1003X  [R_0402_1005Metric]
R15  10 kOhm 1% ERJ-2RKF1002X  [R_0402_1005Metric]
TP4  TP_3V8 DFT_PAD_1P70_NOPASTE_REV_A  [TestPoint_DFT_1.7mm_NoPaste]
TP5  TP_PG_3V8 DFT_PAD_1P70_NOPASTE_REV_A  [TestPoint_DFT_1.7mm_NoPaste]
U3  LMR604403SRAKR 3V8  [LMR60440_RAK0009A]

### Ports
3V3_DIGITAL, 3V8_MODEM, EN_MODEM, GND_PWR, VBAT_SYS

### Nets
3V3_DIGITAL: R15.2 ; port 3V3_DIGITAL
3V8_MODEM: C3.1 C14.1 C15.1 C16.1 L1.2 R1.1 TP4.1(TEST) ; port 3V8_MODEM
BOOT_3V8: C4.1 U3.4(BOOT)
EN_MODEM: R6.1 U3.9(EN) ; port EN_MODEM
FB_3V8: R1.2 R2.1 U3.6(FB)
GND_PWR: C3.2 C11.2 C14.2 C15.2 C16.2 C20.2 R2.2 R3.2 R4.2 R6.2 U3.2(PGND) ; port GND_PWR
MODE_3V8: R4.1 R5.1 U3.7(MODE/SYNC)
PG_3V8: R15.1 TP5.1(TEST) U3.5(PG)
RT_3V8: R3.1 R5.2 U3.8(RT)
SW_3V8: C4.2 L1.1 U3.3(SW)
VBAT_SYS: C11.1 C20.1 U3.1(VIN) ; port VBAT_SYS

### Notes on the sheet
- Explicit wire stubs expose every reviewed pin/net connection. Hierarchical labels are the only cross-sheet connections.

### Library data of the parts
C3 C4 C11 C14-C16 C20 = C
L1 = L
R1-R6 R15 = R
TP4 TP5 = TESTPOINT
U3 = Conn_01x09

## Sheet PCB-PWR_03_3V3_DIGITAL.SchDoc
size 420 x 297 mm
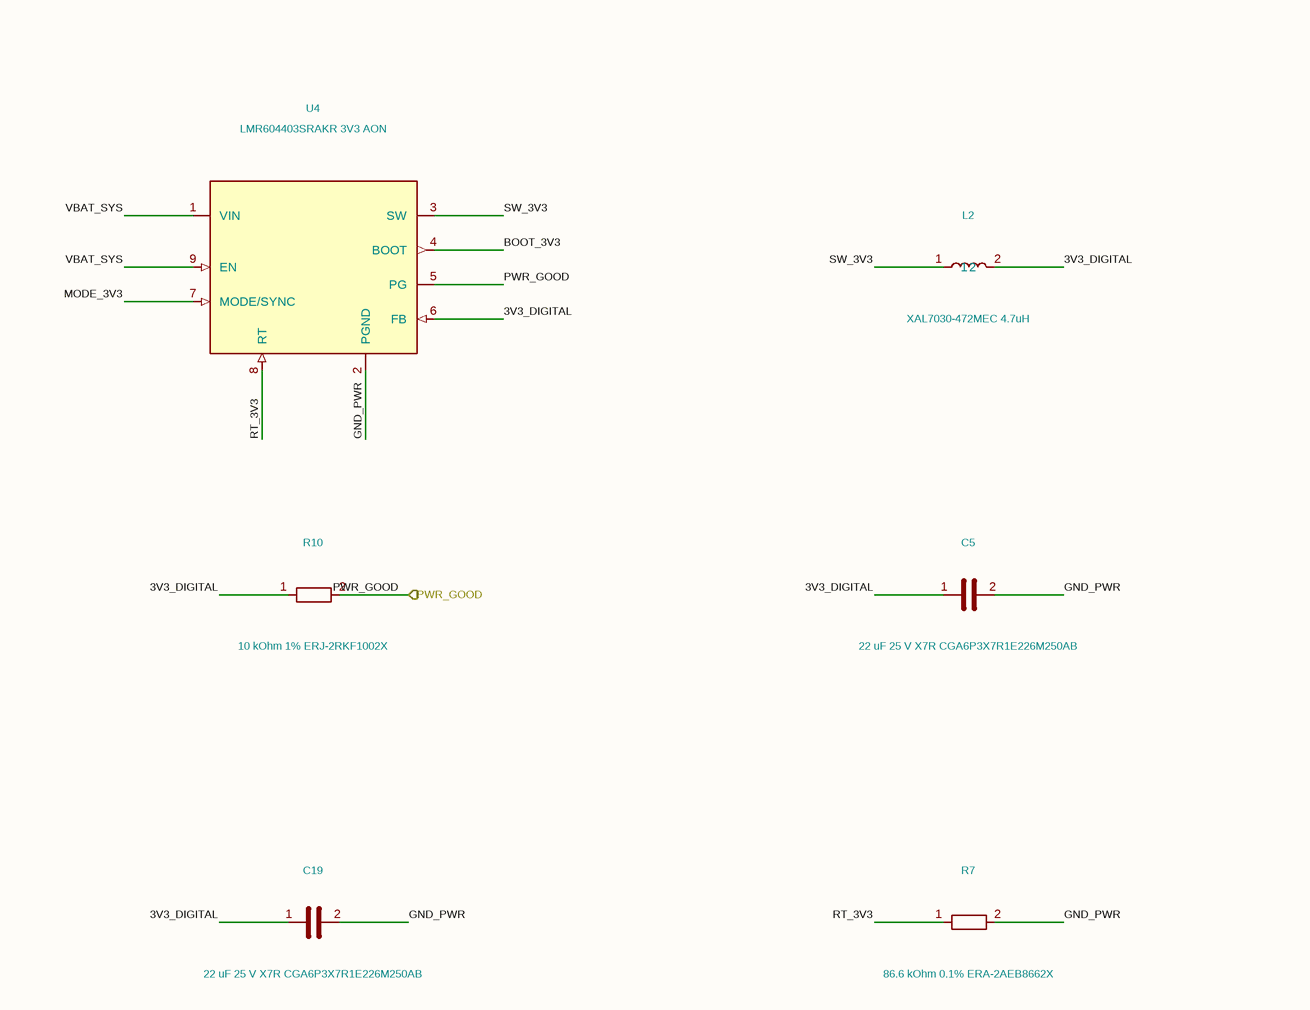
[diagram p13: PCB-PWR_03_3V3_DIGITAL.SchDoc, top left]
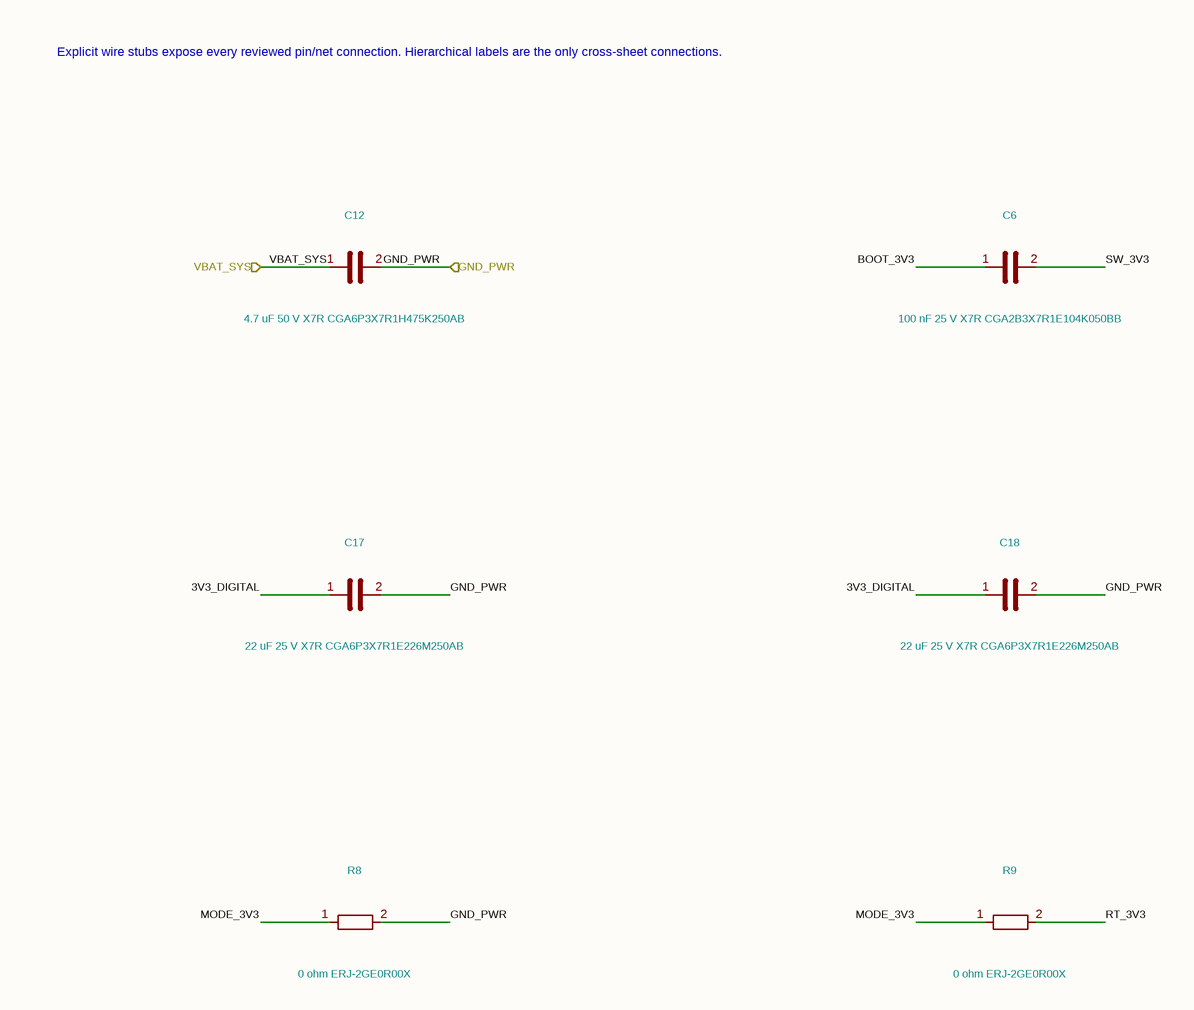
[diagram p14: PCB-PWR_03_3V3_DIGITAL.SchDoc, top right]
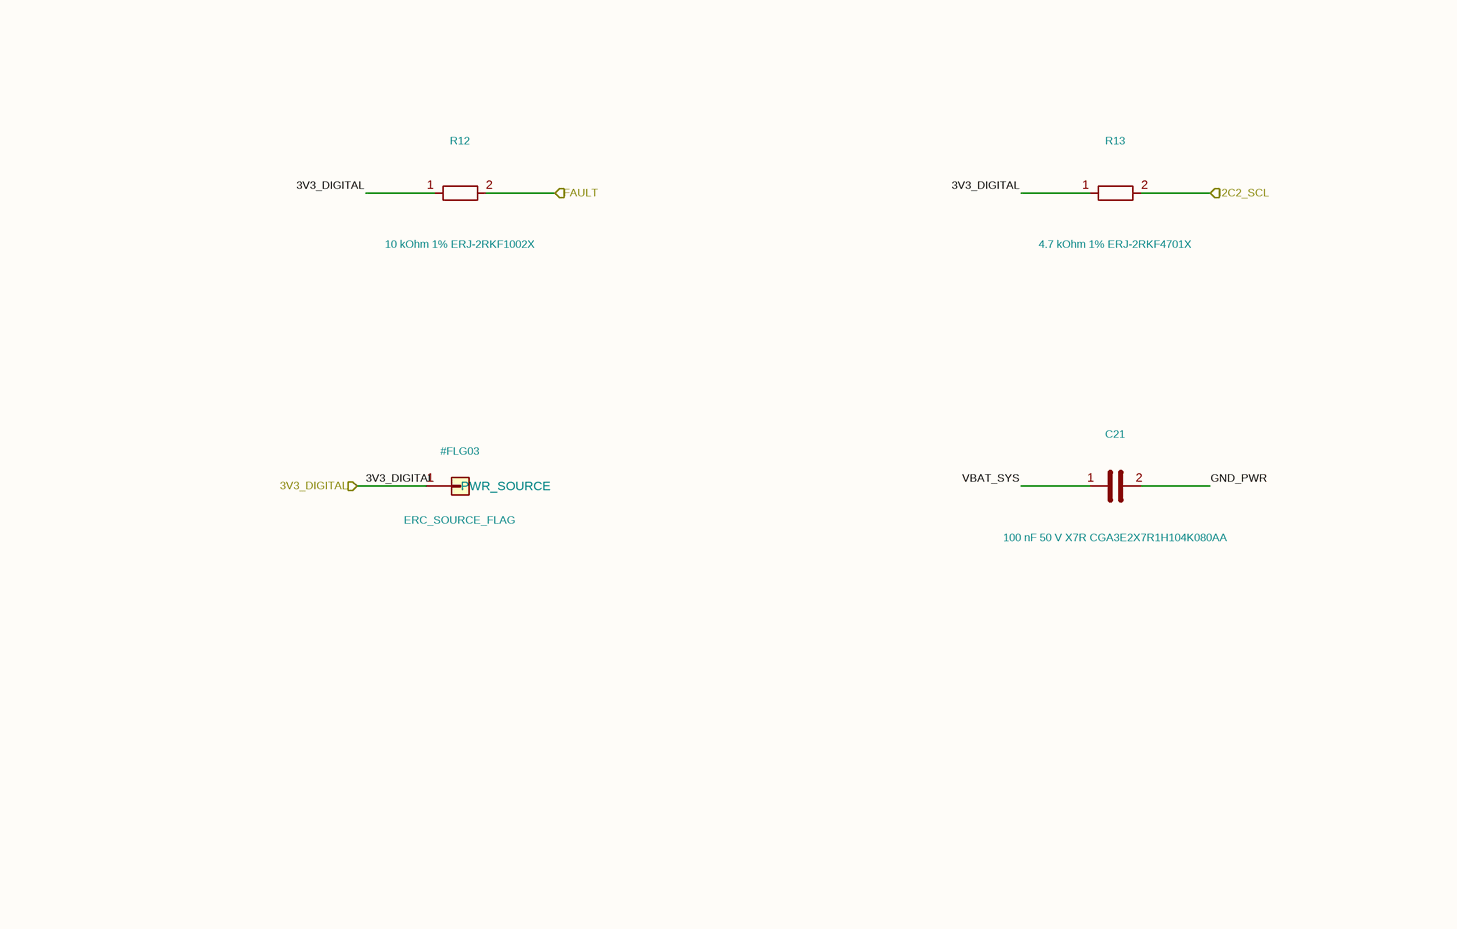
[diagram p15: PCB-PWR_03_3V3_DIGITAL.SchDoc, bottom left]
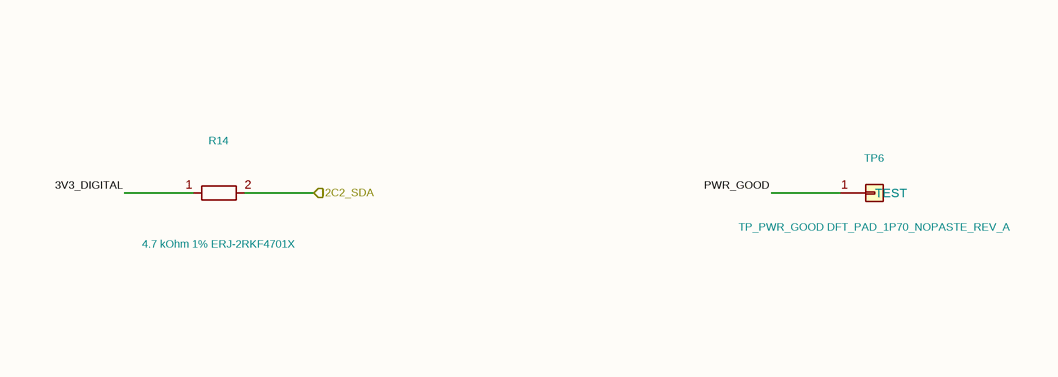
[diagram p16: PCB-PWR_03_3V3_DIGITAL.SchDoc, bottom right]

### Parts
#FLG03  ERC_SOURCE_FLAG
C5  22 uF 25 V X7R CGA6P3X7R1E226M250AB  [C_1210_3225Metric]
C6  100 nF 25 V X7R CGA2B3X7R1E104K050BB  [C_0402_1005Metric]
C12  4.7 uF 50 V X7R CGA6P3X7R1H475K250AB  [C_1210_3225Metric]
C17  22 uF 25 V X7R CGA6P3X7R1E226M250AB  [C_1210_3225Metric]
C18  22 uF 25 V X7R CGA6P3X7R1E226M250AB  [C_1210_3225Metric]
C19  22 uF 25 V X7R CGA6P3X7R1E226M250AB  [C_1210_3225Metric]
C21  100 nF 50 V X7R CGA3E2X7R1H104K080AA  [C_0603_1608Metric]
L2  XAL7030-472MEC 4.7uH  [Coilcraft_XAL7030_472]
R7  86.6 kOhm 0.1% ERA-2AEB8662X  [R_0402_1005Metric]
R8  0 ohm ERJ-2GE0R00X  [R_0402_1005Metric]
R9  0 ohm ERJ-2GE0R00X  [R_0402_1005Metric]
R10  10 kOhm 1% ERJ-2RKF1002X  [R_0402_1005Metric]
R12  10 kOhm 1% ERJ-2RKF1002X  [R_0402_1005Metric]
R13  4.7 kOhm 1% ERJ-2RKF4701X  [R_0402_1005Metric]
R14  4.7 kOhm 1% ERJ-2RKF4701X  [R_0402_1005Metric]
TP6  TP_PWR_GOOD DFT_PAD_1P70_NOPASTE_REV_A  [TestPoint_DFT_1.7mm_NoPaste]
U4  LMR604403SRAKR 3V3 AON  [LMR60440_RAK0009A]

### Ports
3V3_DIGITAL, FAULT, GND_PWR, I2C2_SCL, I2C2_SDA, PWR_GOOD, VBAT_SYS

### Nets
3V3_DIGITAL: #FLG03.1(PWR_SOURCE) C5.1 C17.1 C18.1 C19.1 L2.2 R10.1 R12.1 R13.1 R14.1 U4.6(FB) ; port 3V3_DIGITAL
BOOT_3V3: C6.1 U4.4(BOOT)
FAULT: R12.2 ; port FAULT
GND_PWR: C5.2 C12.2 C17.2 C18.2 C19.2 C21.2 R7.2 R8.2 U4.2(PGND) ; port GND_PWR
I2C2_SCL: R13.2 ; port I2C2_SCL
I2C2_SDA: R14.2 ; port I2C2_SDA
MODE_3V3: R8.1 R9.1 U4.7(MODE/SYNC)
PWR_GOOD: R10.2 TP6.1(TEST) U4.5(PG) ; port PWR_GOOD
RT_3V3: R7.1 R9.2 U4.8(RT)
SW_3V3: C6.2 L2.1 U4.3(SW)
VBAT_SYS: C12.1 C21.1 U4.1(VIN) U4.9(EN) ; port VBAT_SYS

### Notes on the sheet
- Explicit wire stubs expose every reviewed pin/net connection. Hierarchical labels are the only cross-sheet connections.

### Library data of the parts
C5 C6 C12 C17-C19 C21 = C
L2 = L
R7-R10 R12-R14 = R
TP6 = TESTPOINT
U4 = Conn_01x09

## Sheet PCB-PWR_04_AUX_HARNESS.SchDoc
size 420 x 297 mm
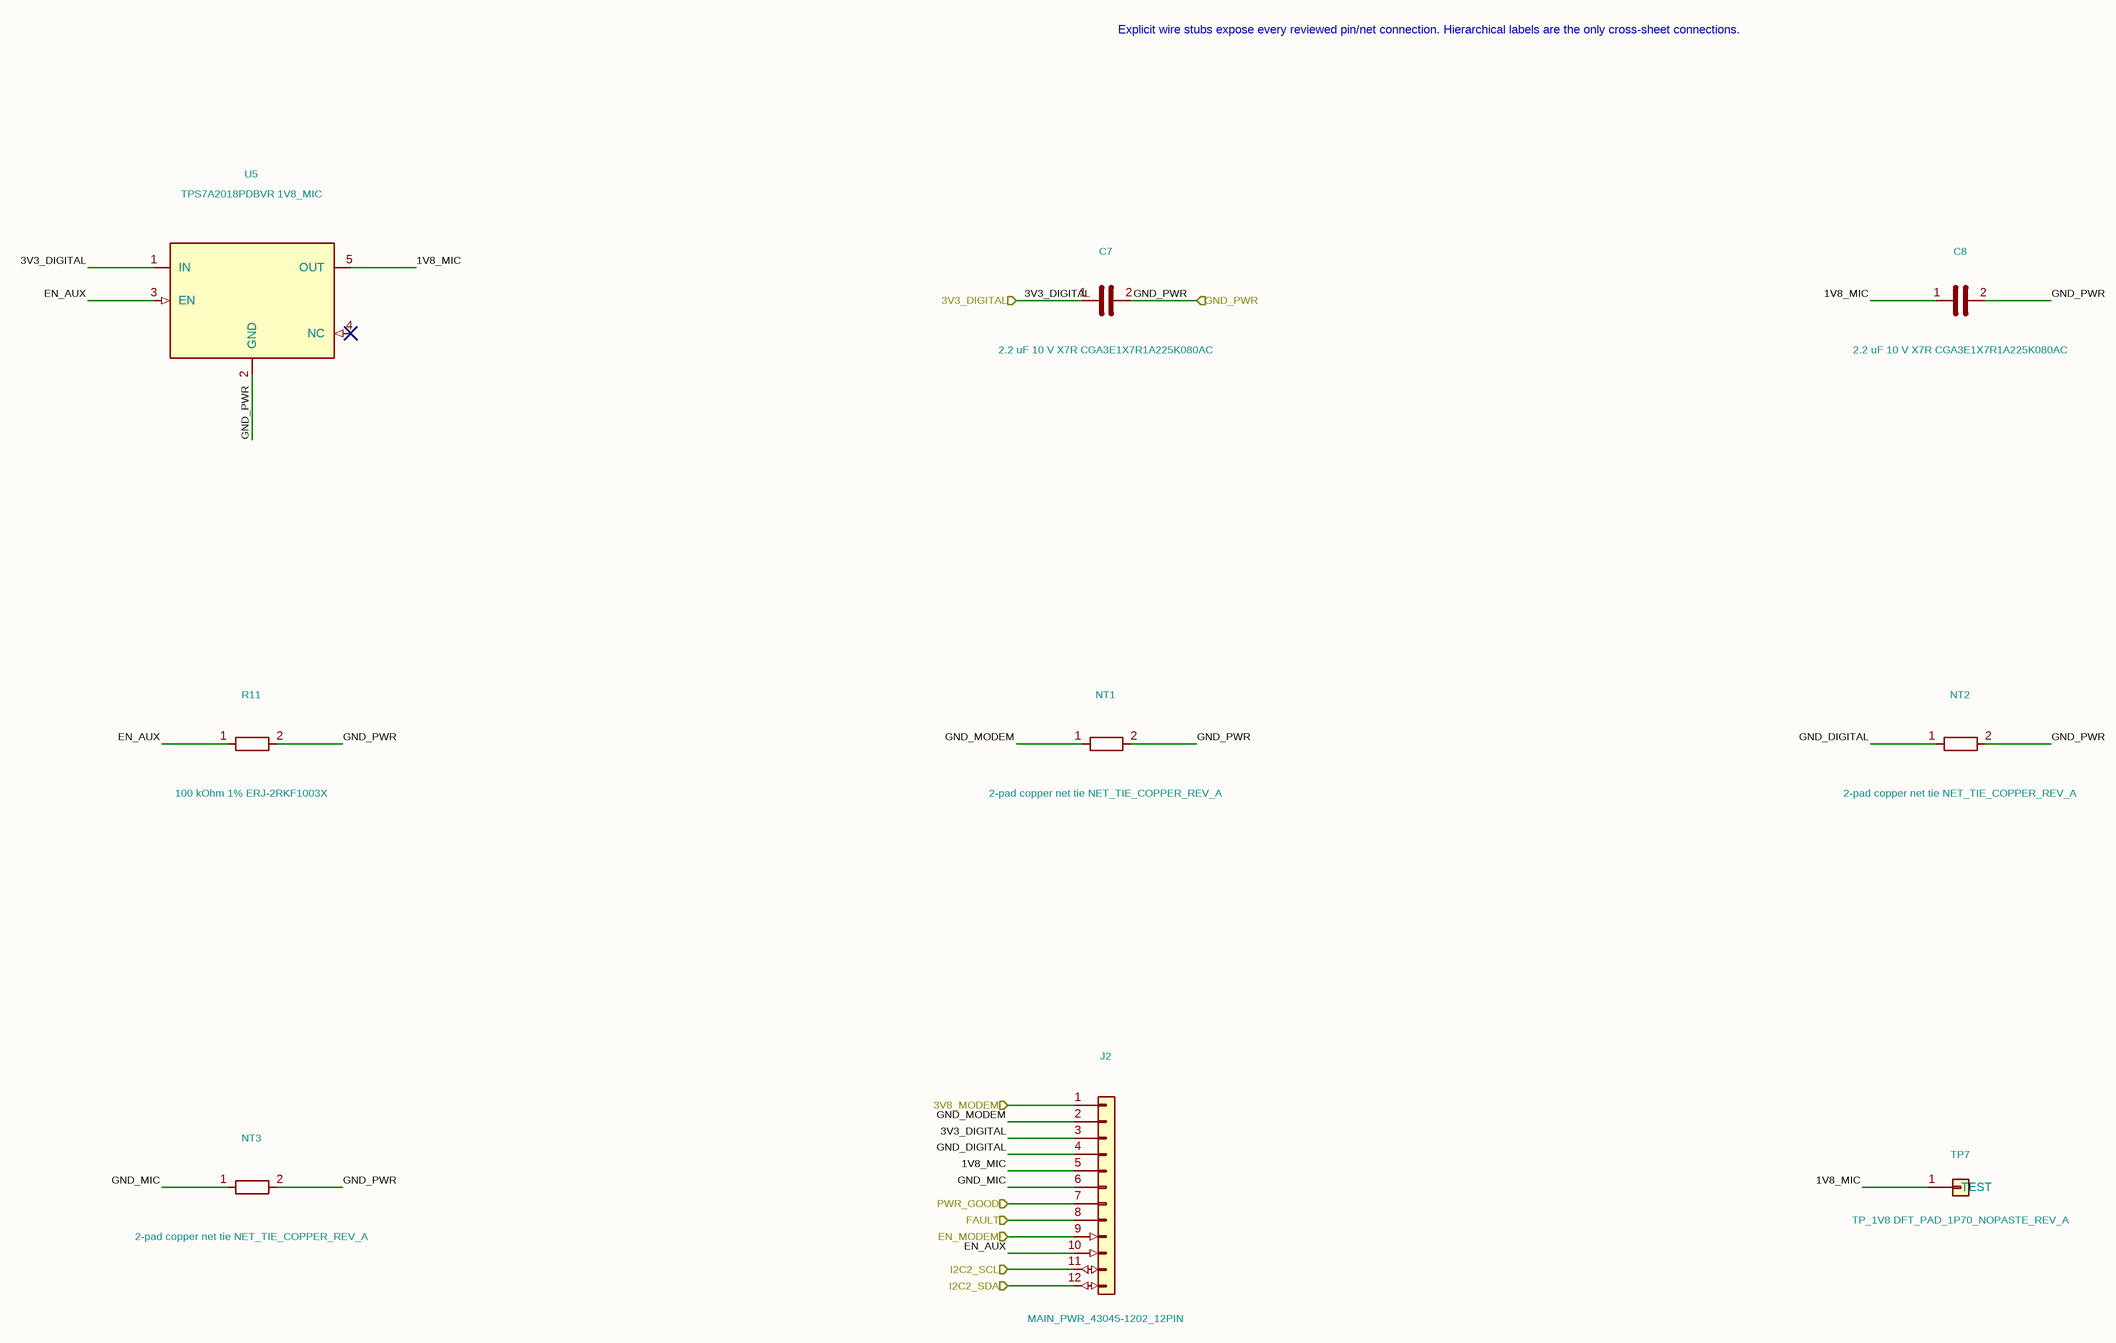
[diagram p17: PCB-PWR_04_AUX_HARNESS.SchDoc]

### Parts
C7  2.2 uF 10 V X7R CGA3E1X7R1A225K080AC  [C_0603_1608Metric]
C8  2.2 uF 10 V X7R CGA3E1X7R1A225K080AC  [C_0603_1608Metric]
J2  MAIN_PWR_43045-1202_12PIN  [Molex_43045-1202_MicroFit-12_RA]
NT1  2-pad copper net tie NET_TIE_COPPER_REV_A  [NetTie-2_SMD_Pad0.5mm]
NT2  2-pad copper net tie NET_TIE_COPPER_REV_A  [NetTie-2_SMD_Pad0.5mm]
NT3  2-pad copper net tie NET_TIE_COPPER_REV_A  [NetTie-2_SMD_Pad0.5mm]
R11  100 kOhm 1% ERJ-2RKF1003X  [R_0402_1005Metric]
TP7  TP_1V8 DFT_PAD_1P70_NOPASTE_REV_A  [TestPoint_DFT_1.7mm_NoPaste]
U5  TPS7A2018PDBVR 1V8_MIC  [TI_DBV0005A_SOT23-5]

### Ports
3V3_DIGITAL, 3V8_MODEM, EN_MODEM, FAULT, GND_PWR, I2C2_SCL, I2C2_SDA, PWR_GOOD

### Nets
1V8_MIC: C8.1 J2.5(1V8_MIC) TP7.1(TEST) U5.5(OUT)
3V3_DIGITAL: C7.1 J2.3(3V3_DIGITAL) U5.1(IN) ; port 3V3_DIGITAL
3V8_MODEM: J2.1(3V8_MODEM) ; port 3V8_MODEM
EN_AUX: J2.10(EN_AUX) R11.1 U5.3(EN)
EN_MODEM: J2.9(EN_MODEM) ; port EN_MODEM
FAULT: J2.8(FAULT) ; port FAULT
GND_DIGITAL: J2.4(GND_DIGITAL) NT2.1
GND_MIC: J2.6(GND_MIC) NT3.1
GND_MODEM: J2.2(GND_MODEM) NT1.1
GND_PWR: C7.2 C8.2 NT1.2 NT2.2 NT3.2 R11.2 U5.2(GND) ; port GND_PWR
I2C2_SCL: J2.11(I2C2_SCL) ; port I2C2_SCL
I2C2_SDA: J2.12(I2C2_SDA) ; port I2C2_SDA
PWR_GOOD: J2.7(PWR_GOOD) ; port PWR_GOOD

Not connected (* = marked no-connect by the designer): U5 4(NC)*

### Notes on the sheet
- Explicit wire stubs expose every reviewed pin/net connection. Hierarchical labels are the only cross-sheet connections.

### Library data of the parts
C7 C8 = C
J2 = Conn_01x12
NT1-NT3 R11 = R
TP7 = TESTPOINT
U5 = Conn_01x05

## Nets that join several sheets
3V3_DIGITAL: PCB-PWR_01_INPUT_PROTECTION (C2.1 U2.6), PCB-PWR_02_3V8_MODEM (R15.2), PCB-PWR_03_3V3_DIGITAL (11 pins), PCB-PWR_04_AUX_HARNESS (C7.1 J2.3 U5.1)
3V8_MODEM: PCB-PWR_02_3V8_MODEM (7 pins), PCB-PWR_04_AUX_HARNESS (J2.1)
EN_MODEM: PCB-PWR_02_3V8_MODEM (R6.1 U3.9), PCB-PWR_04_AUX_HARNESS (J2.9)
FAULT: PCB-PWR_01_INPUT_PROTECTION (TP8.1 U2.3), PCB-PWR_03_3V3_DIGITAL (R12.2), PCB-PWR_04_AUX_HARNESS (J2.8)
GND_PWR: PCB-PWR_01_INPUT_PROTECTION (11 pins), PCB-PWR_02_3V8_MODEM (11 pins), PCB-PWR_03_3V3_DIGITAL (9 pins), PCB-PWR_04_AUX_HARNESS (7 pins)
I2C2_SCL: PCB-PWR_01_INPUT_PROTECTION (TP9.1 U2.5), PCB-PWR_03_3V3_DIGITAL (R13.2), PCB-PWR_04_AUX_HARNESS (J2.11)
I2C2_SDA: PCB-PWR_01_INPUT_PROTECTION (TP10.1 U2.4), PCB-PWR_03_3V3_DIGITAL (R14.2), PCB-PWR_04_AUX_HARNESS (J2.12)
PWR_GOOD: PCB-PWR_03_3V3_DIGITAL (R10.2 TP6.1 U4.5), PCB-PWR_04_AUX_HARNESS (J2.7)
VBAT_SYS: PCB-PWR_01_INPUT_PROTECTION (#FLG01.1 C13.1 RSH1.2 U2.8), PCB-PWR_02_3V8_MODEM (C11.1 C20.1 U3.1), PCB-PWR_03_3V3_DIGITAL (C12.1 C21.1 U4.1 U4.9)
